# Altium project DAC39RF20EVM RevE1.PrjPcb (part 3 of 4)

## Sheet LMK LVL Shift and Mux.SchDoc: <Update Title in Parameters>
size 431 x 279 mm; Date: Not shown in title block; ApprovedBy: Not shown in title block; CheckedBy: Not shown in title block; Author: Not shown in title block; CompanyName: Not shown in title block; Engineer: Not shown in title block; Organization: Not shown in title block; Address1: Not shown in title block; Address2: Not shown in title block; Address3: Not shown in title block; Address4: Not shown in title block; DocumentNumber: 1; Revision: Use project parameter SCH_Rev; SheetNumber: 12; SheetTotal: 21; PageSetup: Record=PageOptions¦CenterHorizontal=True¦CenterVertical=True¦PrintScale=1.00¦XCorrection=1.00¦YCorrection=1.00¦PrintKind=0¦BorderSize=5000000¦LeftOffset=0¦BottomOffset=0¦Orientation=2¦PaperLength=1000¦PaperWidth=1000¦Scale=100¦PaperSource=15¦PrintQuality=600¦MediaType=1¦DitherType=10¦PaperKind=Letter¦PrintScaleMode=1
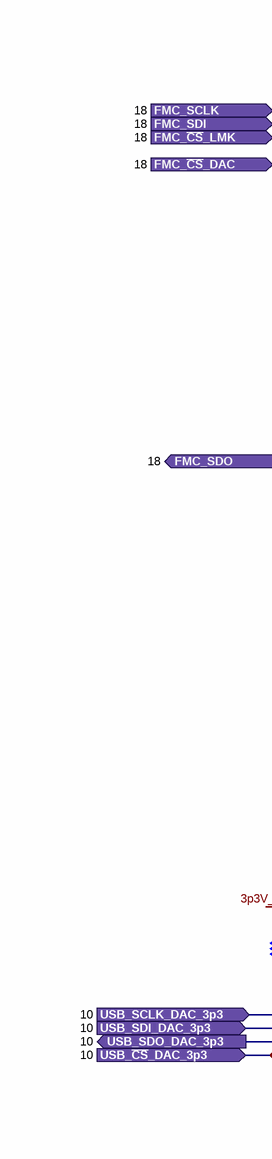
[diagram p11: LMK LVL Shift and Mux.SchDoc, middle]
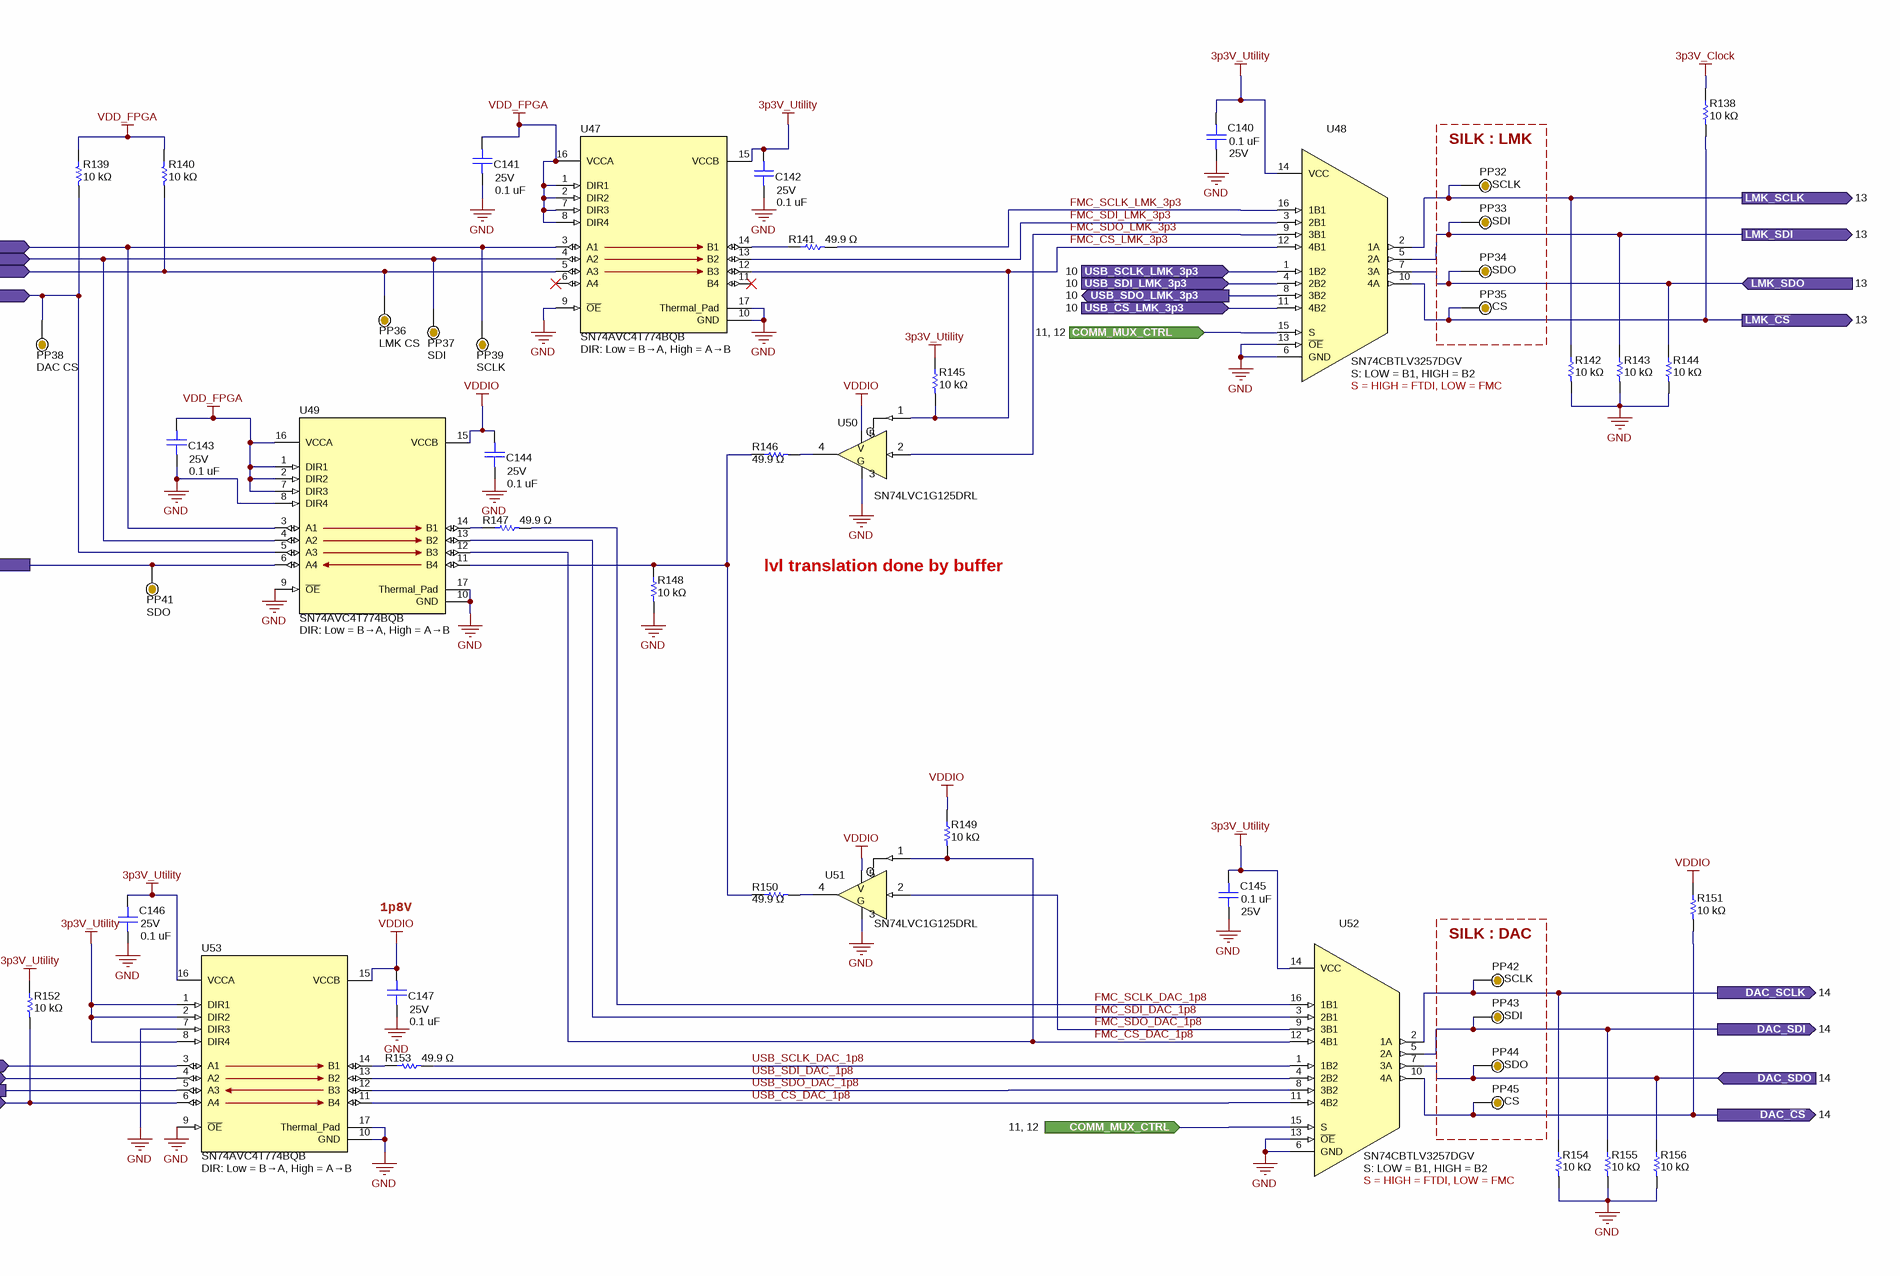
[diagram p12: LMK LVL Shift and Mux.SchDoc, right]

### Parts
C140  value 0.1 uF  Voltage - Rated: 25V  [0402L_cap]  (hidden comment: GRT155R71E104KE01J)
C141  value 0.1 uF  Voltage - Rated: 25V  [0402L_cap]  (hidden comment: GRT155R71E104KE01J)
C142  value 0.1 uF  Voltage - Rated: 25V  [0402L_cap]  (hidden comment: GRT155R71E104KE01J)
C143  value 0.1 uF  Voltage - Rated: 25V  [0402L_cap]  (hidden comment: GRT155R71E104KE01J)
C144  value 0.1 uF  Voltage - Rated: 25V  [0402L_cap]  (hidden comment: GRT155R71E104KE01J)
C145  value 0.1 uF  Voltage - Rated: 25V  [0402L_cap]  (hidden comment: GRT155R71E104KE01J)
C146  value 0.1 uF  Voltage - Rated: 25V  [0402L_cap]  (hidden comment: GRT155R71E104KE01J)
C147  value 0.1 uF  Voltage - Rated: 25V  [0402L_cap]  (hidden comment: GRT155R71E104KE01J)
PP32  Text1: SCLK  [ProbePoint_TH_40mil]  (hidden comment: Probe Point)  (no BOM)
PP33  Text1: SDI  [ProbePoint_TH_40mil]  (hidden comment: Probe Point)  (no BOM)
PP34  Text1: SDO  [ProbePoint_TH_40mil]  (hidden comment: Probe Point)  (no BOM)
PP35  Text1: CS  [ProbePoint_TH_40mil]  (hidden comment: Probe Point)  (no BOM)
PP36  Text1: LMK CS  [ProbePoint_TH_40mil]  (hidden comment: Probe Point)  (no BOM)
PP37  Text1: SDI  [ProbePoint_TH_40mil]  (hidden comment: Probe Point)  (no BOM)
PP38  Text1: DAC CS  [ProbePoint_TH_40mil]  (hidden comment: Probe Point)  (no BOM)
PP39  Text1: SCLK  [ProbePoint_TH_40mil]  (hidden comment: Probe Point)  (no BOM)
PP41  Text1: SDO  [ProbePoint_TH_40mil]  (hidden comment: Probe Point)  (no BOM)
PP42  Text1: SCLK  [ProbePoint_TH_40mil]  (hidden comment: Probe Point)  (no BOM)
PP43  Text1: SDI  [ProbePoint_TH_40mil]  (hidden comment: Probe Point)  (no BOM)
PP44  Text1: SDO  [ProbePoint_TH_40mil]  (hidden comment: Probe Point)  (no BOM)
PP45  Text1: CS  [ProbePoint_TH_40mil]  (hidden comment: Probe Point)  (no BOM)
R138  value 10 kΩ  [0201]  (hidden comment: ERJ-1GNF1002C)
R139  value 10 kΩ  [0201]  (hidden comment: ERJ-1GNF1002C)
R140  value 10 kΩ  [0201]  (hidden comment: ERJ-1GNF1002C)
R141  value 49.9 Ω  [0201]  (hidden comment: ERJ-1GNF49R9C)
R142  value 10 kΩ  [0201]  (hidden comment: ERJ-1GNF1002C)
R143  value 10 kΩ  [0201]  (hidden comment: ERJ-1GNF1002C)
R144  value 10 kΩ  [0201]  (hidden comment: ERJ-1GNF1002C)
R145  value 10 kΩ  [0201]  (hidden comment: ERJ-1GNF1002C)
R146  value 49.9 Ω  [0201]  (hidden comment: ERJ-1GNF49R9C)
R147  value 49.9 Ω  [0201]  (hidden comment: ERJ-1GNF49R9C)
R148  value 10 kΩ  [0201]  (hidden comment: ERJ-1GNF1002C)
R149  value 10 kΩ  [0201]  (hidden comment: ERJ-1GNF1002C)
R150  value 49.9 Ω  [0201]  (hidden comment: ERJ-1GNF49R9C)
R151  value 10 kΩ  [0201]  (hidden comment: ERJ-1GNF1002C)
R152  value 10 kΩ  [0201]  (hidden comment: ERJ-1GNF1002C)
R153  value 49.9 Ω  [0201]  (hidden comment: ERJ-1GNF49R9C)
R154  value 10 kΩ  [0201]  (hidden comment: ERJ-1GNF1002C)
R155  value 10 kΩ  [0201]  (hidden comment: ERJ-1GNF1002C)
R156  value 10 kΩ  [0201]  (hidden comment: ERJ-1GNF1002C)
U47  SN74AVC4T774BQB  Text1: DIR: Low = B→A, High = A→B  [BQB0016A-MFG]
U48  SN74CBTLV3257DGV  Text1: S: LOW = B1, HIGH = B2  [RSV0016A]
U49  SN74AVC4T774BQB  Text1: DIR: Low = B→A, High = A→B  [BQB0016A-MFG]
U50  SN74LVC1G125DRL  [DRL0005A]
U51  SN74LVC1G125DRL  [DRL0005A]
U52  SN74CBTLV3257DGV  Text1: S: LOW = B1, HIGH = B2  [RSV0016A]
U53  SN74AVC4T774BQB  Text1: DIR: Low = B→A, High = A→B  [BQB0016A-MFG]

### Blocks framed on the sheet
SILK : LMK: PP32-PP35
SILK : DAC: PP42-PP45

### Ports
COMM_MUX_CTRL (in, see 11, 12), DAC_SCLK (out, see 14), DAC_SDI (out, see 14), DAC_SDO (in, see 14), DAC_~{CS} (out, see 14), FMC_SCLK (in, see 18), FMC_SDI (in, see 18), FMC_SDO (out, see 18), FMC_~{CS}_DAC (in, see 18), FMC_~{CS}_LMK (in, see 18), LMK_SCLK (out, see 13), LMK_SDI (out, see 13), LMK_SDO (in, see 13), LMK_~{CS} (out, see 13), USB_SCLK_DAC_3p3 (in, see 10), USB_SCLK_LMK_3p3 (in, see 10), USB_SDI_DAC_3p3 (in, see 10), USB_SDI_LMK_3p3 (in, see 10), USB_SDO_DAC_3p3 (out, see 10), USB_SDO_LMK_3p3 (out, see 10), USB_~{CS}_DAC_3p3 (in, see 10), USB_~{CS}_LMK_3p3 (in, see 10)

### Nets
3p3V_Clock: R138.1
3p3V_Utility: C140.2 C142.1 C145.2 C146.2 R145.1 R152.1 U47.15(VCCB) U48.14(VCC) U52.14(VCC) U53.1(DIR1) U53.2(DIR2) U53.8(DIR4) U53.16(VCCA)
GND: C140.1 C141.2 C142.2 C143.2 C144.2 C145.1 C146.1 C147.2 R142.2 R143.2 R144.2 R148.2 R154.2 R155.2 R156.2 U47.9(~{OE}) U47.10(GND) U47.17(Thermal_Pad) U48.6(GND) U48.13(~{OE}) U49.8(DIR4) U49.9(~{OE}) U49.10(GND) U49.17(Thermal_Pad) U50.3(GND) U51.3(GND) U52.6(GND) U52.13(~{OE}) U53.7(DIR3) U53.9(~{OE}) U53.10(GND) U53.17(Thermal_Pad)
VDD_FPGA: C141.1 C143.1 R139.1 R140.1 U47.1(DIR1) U47.2(DIR2) U47.7(DIR3) U47.8(DIR4) U47.16(VCCA) U49.1(DIR1) U49.2(DIR2) U49.7(DIR3) U49.16(VCCA)
VDDIO: C144.1 C147.1 R149.1 R151.1 U49.15(VCCB) U50.5(VCC) U51.5(VCC) U53.15(VCCB)
COMM_MUX_CTRL: U48.15(S) U52.15(S) ; port COMM_MUX_CTRL
DAC_~{CS}: PP45.1 R151.2 U52.10(4A) ; port DAC_~{CS}
DAC_SCLK: PP42.1 R154.1 U52.2(1A) ; port DAC_SCLK
DAC_SDI: PP43.1 R155.1 U52.5(2A) ; port DAC_SDI
DAC_SDO: PP44.1 R156.1 U52.7(3A) ; port DAC_SDO
FMC_~{CS}_DAC: PP38.1 R139.2 U49.5(A3) ; port FMC_~{CS}_DAC
FMC_~{CS}_LMK: PP36.1 R140.2 U47.5(A3) ; port FMC_~{CS}_LMK
FMC_~{CS}_LMK_3p3: R145.2 U47.12(B3) U48.12(4B1) U50.1(~{OE})
FMC_CS_DAC_1p8: R149.2 U49.12(B3) U51.1(~{OE}) U52.12(4B1)
FMC_SCLK: PP39.1 U47.3(A1) U49.3(A1) ; port FMC_SCLK
FMC_SCLK_DAC_1p8: R147.2 U52.16(1B1)
FMC_SCLK_LMK_3p3: R141.2 U48.16(1B1)
FMC_SDI: PP37.1 U47.4(A2) U49.4(A2) ; port FMC_SDI
FMC_SDI_DAC_1p8: U49.13(B2) U52.3(2B1)
FMC_SDI_LMK_3p3: U47.13(B2) U48.3(2B1)
FMC_SDO: PP41.1 U49.6(A4) ; port FMC_SDO
FMC_SDO_DAC_1p8: U51.2(A) U52.9(3B1)
FMC_SDO_LMK_3p3: U48.9(3B1) U50.2(A)
LMK_~{CS}: PP35.1 R138.2 U48.10(4A) ; port LMK_~{CS}
LMK_SCLK: PP32.1 R142.1 U48.2(1A) ; port LMK_SCLK
LMK_SDI: PP33.1 R143.1 U48.5(2A) ; port LMK_SDI
LMK_SDO: PP34.1 R144.1 U48.7(3A) ; port LMK_SDO
USB_~{CS}_DAC_3p3: R152.2 U53.6(A4) ; port USB_~{CS}_DAC_3p3
USB_~{CS}_LMK_3p3: U48.11(4B2) ; port USB_~{CS}_LMK_3p3
USB_CS_DAC_1p8: U52.11(4B2) U53.11(B4)
USB_SCLK_DAC_1p8: R153.2 U52.1(1B2)
USB_SCLK_DAC_3p3: U53.3(A1) ; port USB_SCLK_DAC_3p3
USB_SCLK_LMK_3p3: U48.1(1B2) ; port USB_SCLK_LMK_3p3
USB_SDI_DAC_1p8: U52.4(2B2) U53.13(B2)
USB_SDI_DAC_3p3: U53.4(A2) ; port USB_SDI_DAC_3p3
USB_SDI_LMK_3p3: U48.4(2B2) ; port USB_SDI_LMK_3p3
USB_SDO_DAC_1p8: U52.8(3B2) U53.12(B3)
USB_SDO_DAC_3p3: U53.5(A3) ; port USB_SDO_DAC_3p3
USB_SDO_LMK_3p3: U48.8(3B2) ; port USB_SDO_LMK_3p3
NetR141_1: R141.1 U47.14(B1)
NetR146_1: R146.1 R148.1 R150.1 U49.11(B4)
NetR146_2: R146.2 U50.4(Y)
NetR147_1: R147.1 U49.14(B1)
NetR150_2: R150.2 U51.4(Y)
NetR153_1: R153.1 U53.14(B1)

Not connected (* = marked no-connect by the designer): U47 6(A4)* 11(B4)*

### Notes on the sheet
- (near U48) S = HIGH = FTDI, LOW = FMC
- lvl translation done by buffer
- 1p8V
- (near U52) S = HIGH = FTDI, LOW = FMC

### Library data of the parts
C140-C147 = capcc09401: CAP CER 0.1UF 25V X7R 0402; Manufacturer: Murata; SizeZ_mm: 0.7; SizeX_mm: 1; SizeY_mm: 0.5; CompType: Capacitor Ceramic; Tolerance: ±10%
PP32-PP39 PP41-PP45 = Probe Point: Probe Point that can be used in lue of a test point; UniqueID: cmp00025
R138-R140 R142-R145 R148 R149 R151 R152 R154-R156 = RSMD020100762: RES SMD 10K OHM 1% 1/20W 0201; Manufacturer: Panasonic Electronic Components; CompType: Resistor SMD; Power (Watts): 0.05W, 1/20W; Temperature Coefficient: ±200ppm/°C
R141 R146 R147 R150 R153 = RSMD020100177: RES SMD 49.9 OHM 1% 1/20W 0201; Manufacturer: Panasonic Electronic Components; CompType: Resistor SMD; Power (Watts): 0.05W, 1/20W; Temperature Coefficient: ±200ppm/°C
U47 U49 U53 = cmp00170: Translation - Voltage Levels 4-bit dual-supply bus transceiver with 3-state outputs and independent direction control inputs; Manufacturer: Texas Instruments; Alt PartNumber: SN74AXC4T774BQB; CompType: Level Shifter
U48 U52 = SN74CBTLV3257RSV: Low-Voltage 4-Bit 1-of-2 FET Multiplexer/Demultiplexe; PartNumber: SN74CBTLV3257RSVR; Manufacturer: Texas Instruments; UniqueID: cmp00269; CompType: MUX
U50 U51 = SN74LVC1G125DRL: Single Bus Buffer Gate With 3-State Outputs; Manufacturer: Texas Instruments; UniqueID: cmp00472

## Sheet Clocking LMK04828.SchDoc: LMK Clocking Fanout
size 431 x 279 mm; Date: Not shown in title block; ApprovedBy: Not shown in title block; CheckedBy: Not shown in title block; Author: Not shown in title block; CompanyName: Not shown in title block; Engineer: Not shown in title block; Organization: Not shown in title block; Address1: Not shown in title block; Address2: Not shown in title block; Address3: Not shown in title block; Address4: Not shown in title block; DocumentNumber: 1; Revision: Use project parameter SCH_Rev; SheetNumber: 13; SheetTotal: 21; PageSetup: Record=PageOptions¦CenterHorizontal=True¦CenterVertical=True¦PrintScale=1.00¦XCorrection=1.00¦YCorrection=1.00¦PrintKind=0¦BorderSize=5000000¦LeftOffset=0¦BottomOffset=0¦Orientation=2¦PaperLength=1000¦PaperWidth=1000¦Scale=100¦PaperSource=15¦PrintQuality=600¦MediaType=1¦DitherType=10¦PaperKind=Letter¦PrintScaleMode=1
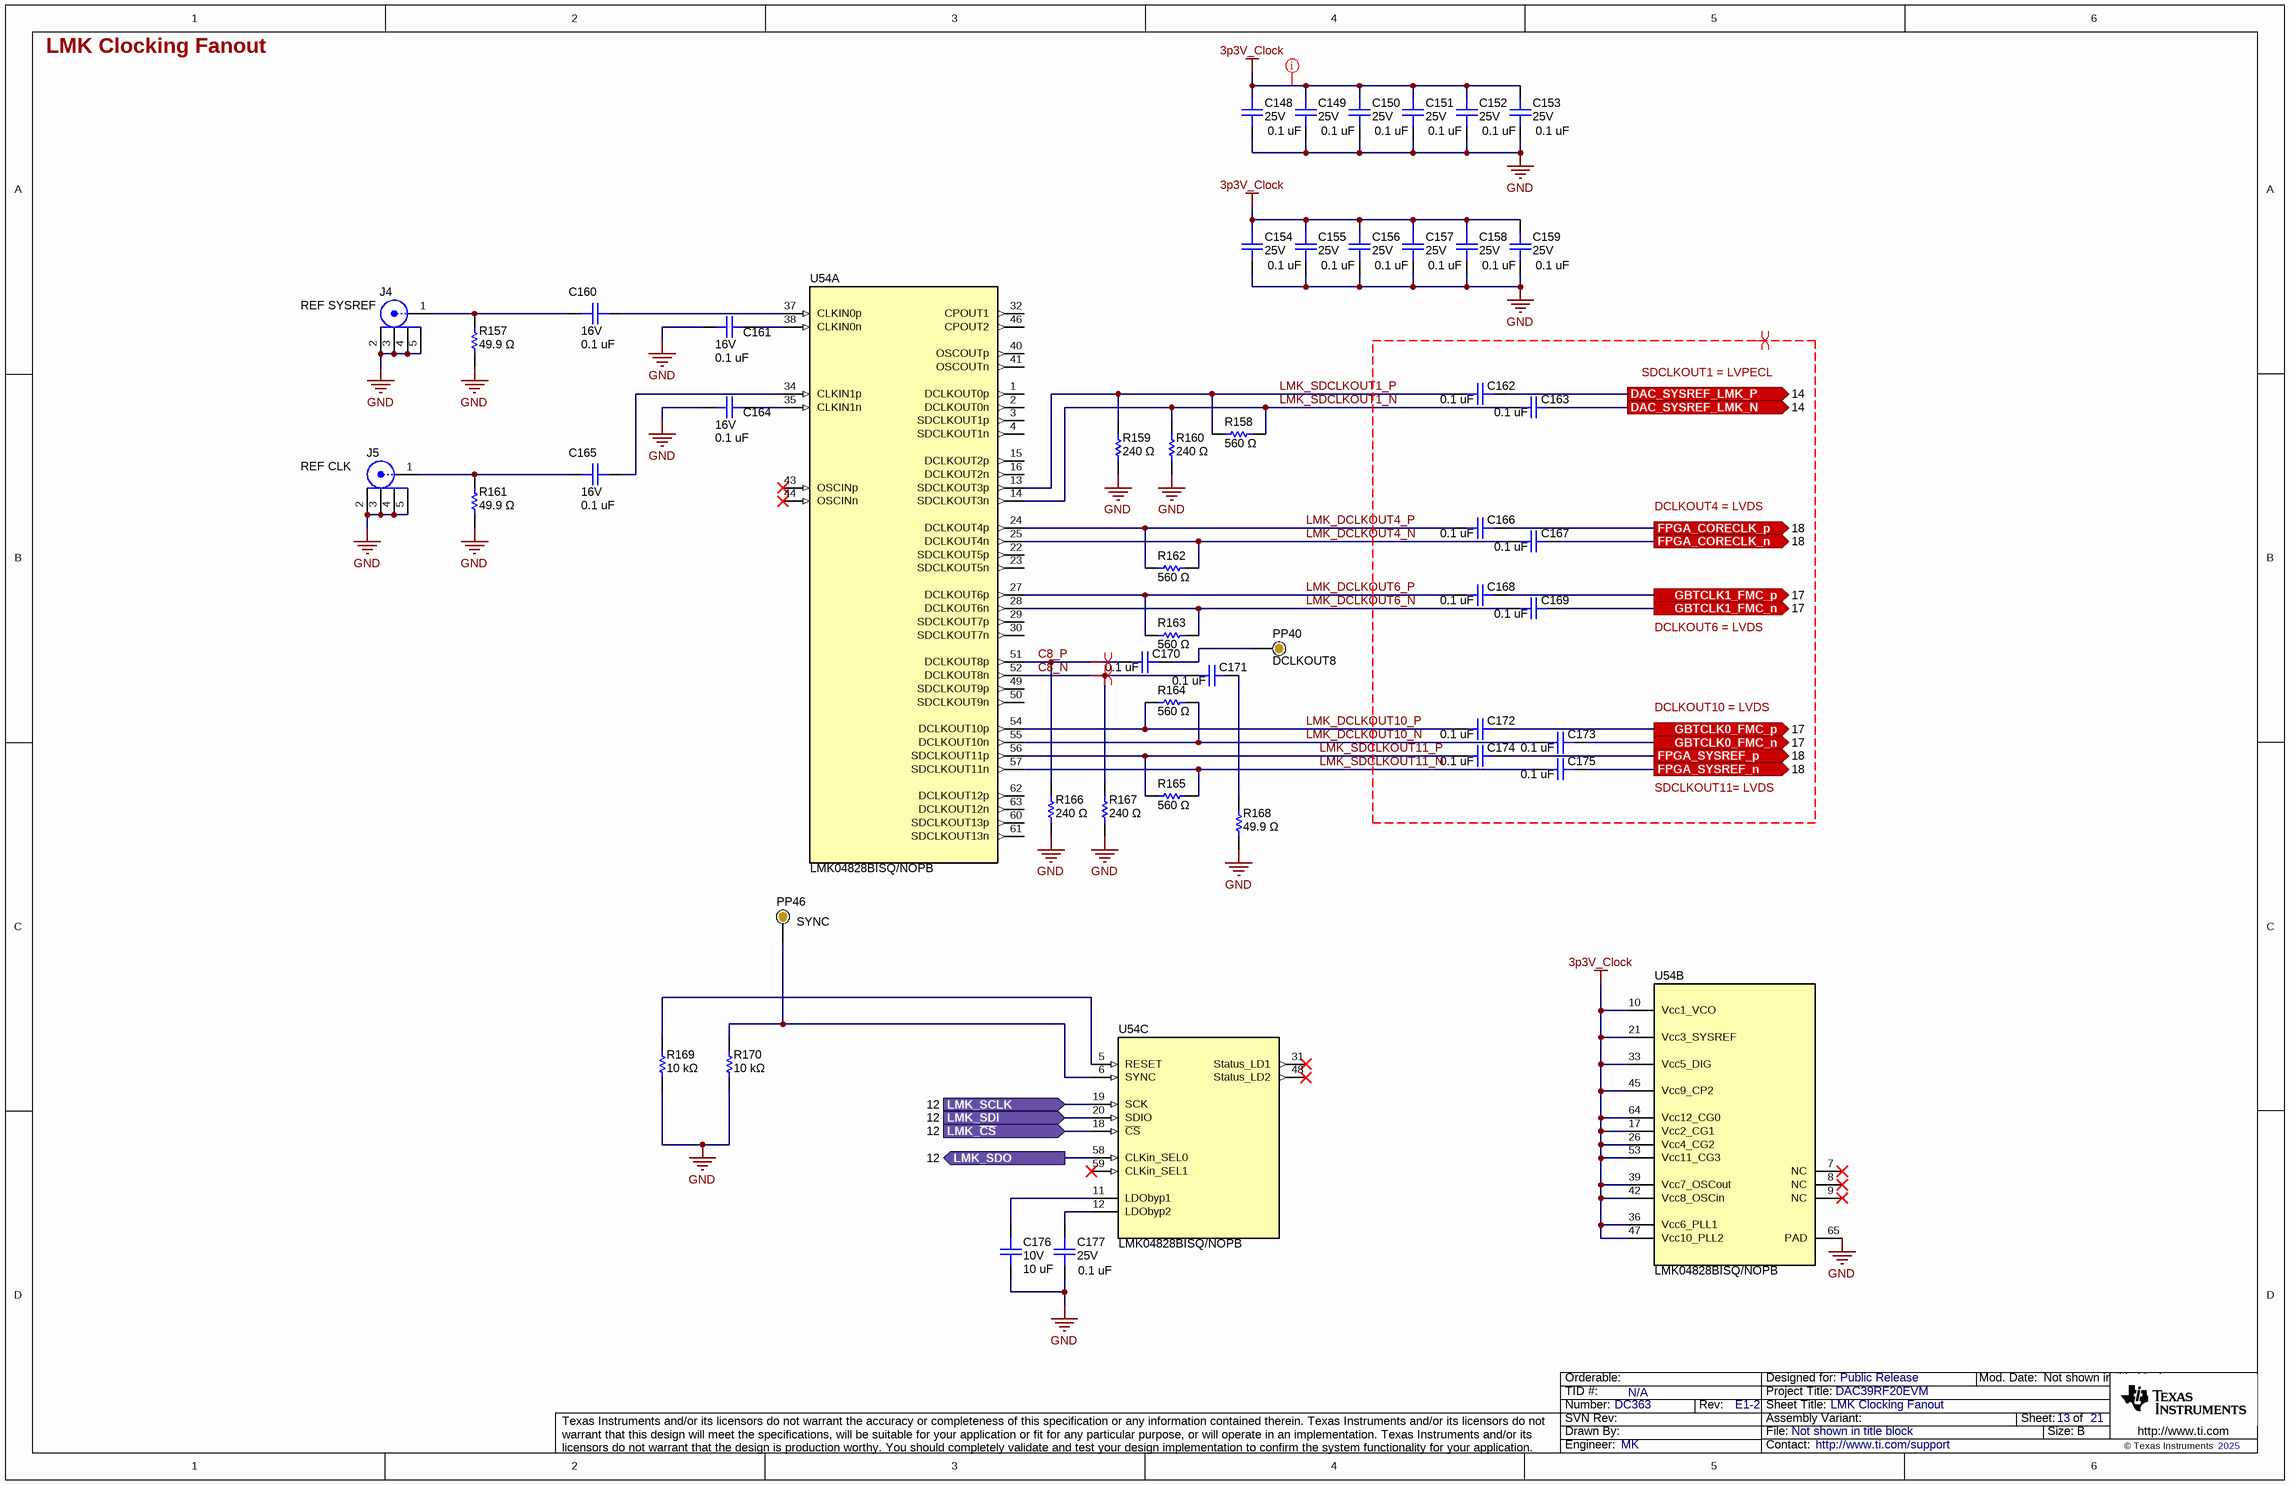
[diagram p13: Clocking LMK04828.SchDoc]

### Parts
C148  value 0.1 uF  Voltage - Rated: 25V  [0402L_cap]  (hidden comment: GRT155R71E104KE01J)
C149  value 0.1 uF  Voltage - Rated: 25V  [0402L_cap]  (hidden comment: GRT155R71E104KE01J)
C150  value 0.1 uF  Voltage - Rated: 25V  [0402L_cap]  (hidden comment: GRT155R71E104KE01J)
C151  value 0.1 uF  Voltage - Rated: 25V  [0402L_cap]  (hidden comment: GRT155R71E104KE01J)
C152  value 0.1 uF  Voltage - Rated: 25V  [0402L_cap]  (hidden comment: GRT155R71E104KE01J)
C153  value 0.1 uF  Voltage - Rated: 25V  [0402L_cap]  (hidden comment: GRT155R71E104KE01J)
C154  value 0.1 uF  Voltage - Rated: 25V  [0402L_cap]  (hidden comment: GRT155R71E104KE01J)
C155  value 0.1 uF  Voltage - Rated: 25V  [0402L_cap]  (hidden comment: GRT155R71E104KE01J)
C156  value 0.1 uF  Voltage - Rated: 25V  [0402L_cap]  (hidden comment: GRT155R71E104KE01J)
C157  value 0.1 uF  Voltage - Rated: 25V  [0402L_cap]  (hidden comment: GRT155R71E104KE01J)
C158  value 0.1 uF  Voltage - Rated: 25V  [0402L_cap]  (hidden comment: GRT155R71E104KE01J)
C159  value 0.1 uF  Voltage - Rated: 25V  [0402L_cap]  (hidden comment: GRT155R71E104KE01J)
C160  value 0.1 uF  Voltage - Rated: 16V  [0201_cap]  (hidden comment: GRM033Z71C104KE14D)
C161  value 0.1 uF  Voltage - Rated: 16V  [0201_cap]  (hidden comment: GRM033Z71C104KE14D)
C162  value 0.1 uF  [0201_cap]  (hidden comment: GRM033Z71C104KE14D)
C163  value 0.1 uF  [0201_cap]  (hidden comment: GRM033Z71C104KE14D)
C164  value 0.1 uF  Voltage - Rated: 16V  [0201_cap]  (hidden comment: GRM033Z71C104KE14D)
C165  value 0.1 uF  Voltage - Rated: 16V  [0201_cap]  (hidden comment: GRM033Z71C104KE14D)
C166  value 0.1 uF  [0201_cap]  (hidden comment: GRM033Z71C104KE14D)
C167  value 0.1 uF  [0201_cap]  (hidden comment: GRM033Z71C104KE14D)
C168  value 0.1 uF  [0201_cap]  (hidden comment: GRM033Z71C104KE14D)
C169  value 0.1 uF  [0201_cap]  (hidden comment: GRM033Z71C104KE14D)
C170  value 0.1 uF  [0201_cap]  (hidden comment: GRM033Z71C104KE14D)
C171  value 0.1 uF  [0201_cap]  (hidden comment: GRM033Z71C104KE14D)
C172  value 0.1 uF  [0201_cap]  (hidden comment: GRM033Z71C104KE14D)
C173  value 0.1 uF  [0201_cap]  (hidden comment: GRM033Z71C104KE14D)
C174  value 0.1 uF  [0201_cap]  (hidden comment: GRM033Z71C104KE14D)
C175  value 0.1 uF  [0201_cap]  (hidden comment: GRM033Z71C104KE14D)
C176  value 10 uF  Voltage - Rated: 10V  [0603L_cap]  (hidden comment: C1608X5R1A106K080AC)
C177  value 0.1 uF  Voltage - Rated: 25V  [0402L_cap]  (hidden comment: GRT155R71E104KE01J)
J4  Text1: REF SYSREF  [FP-132134-15_CONN_SMA_JACK-MFG]  (hidden comment: 132134-15)
J5  Text1: REF CLK  [FP-132134-15_CONN_SMA_JACK-MFG]  (hidden comment: 132134-15)
PP40  Text1: DCLKOUT8  [ProbePoint_TH_40mil]  (hidden comment: Probe Point)  (no BOM)
PP46  Text1: SYNC  [ProbePoint_TH_40mil]  (hidden comment: Probe Point)  (no BOM)
R157  value 49.9 Ω  [0201]  (hidden comment: ERJ-1GNF49R9C)
R158  value 560 Ω  [0201]  (hidden comment: ERJ-U01J561C)
R159  value 240 Ω  [0201]  (hidden comment: ERJ-1GNF2400C)
R160  value 240 Ω  [0201]  (hidden comment: ERJ-1GNF2400C)
R161  value 49.9 Ω  [0201]  (hidden comment: ERJ-1GNF49R9C)
R162  value 560 Ω  [0201]  (hidden comment: ERJ-U01J561C)
R163  value 560 Ω  [0201]  (hidden comment: ERJ-U01J561C)
R164  value 560 Ω  [0201]  (hidden comment: ERJ-U01J561C)
R165  value 560 Ω  [0201]  (hidden comment: ERJ-U01J561C)
R166  value 240 Ω  [0201]  (hidden comment: ERJ-1GNF2400C)
R167  value 240 Ω  [0201]  (hidden comment: ERJ-1GNF2400C)
R168  value 49.9 Ω  [0201]  (hidden comment: ERJ-1GNF49R9C)
R169  value 10 kΩ  [0402L]  (hidden comment: ERJ-H2RF1002X)
R170  value 10 kΩ  [0402L]  (hidden comment: ERJ-H2RF1002X)
U54  LMK04828BISQ/NOPB  [NKD0064A]  (parts A,B,C of 3)

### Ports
DAC_SYSREF_LMK_N (out, see 14), DAC_SYSREF_LMK_P (out, see 14), FPGA_CORECLK_n (out, see 18), FPGA_CORECLK_p (out, see 18), FPGA_SYSREF_n (out, see 18), FPGA_SYSREF_p (out, see 18), GBTCLK0_FMC_n (out, see 17), GBTCLK0_FMC_p (out, see 17), GBTCLK1_FMC_n (out, see 17), GBTCLK1_FMC_p (out, see 17), LMK_SCLK (in, see 12), LMK_SDI (in, see 12), LMK_SDO (out, see 12), LMK_~{CS} (in, see 12)

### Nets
3p3V_Clock: C148.1 C149.1 C150.1 C151.1 C152.1 C153.1 C154.1 C155.1 C156.1 C157.1 C158.1 C159.1 U54.10(Vcc1_VCO) U54.17(Vcc2_CG1) U54.21(Vcc3_SYSREF) U54.26(Vcc4_CG2) U54.33(Vcc5_DIG) U54.36(Vcc6_PLL1) U54.39(Vcc7_OSCout) U54.42(Vcc8_OSCin) U54.45(Vcc9_CP2) U54.47(Vcc10_PLL2) U54.53(Vcc11_CG3) U54.64(Vcc12_CG0)
GND: C148.2 C149.2 C150.2 C151.2 C152.2 C153.2 C154.2 C155.2 C156.2 C157.2 C158.2 C159.2 C161.1 C164.1 C176.1 C177.2 J4.2 J4.3 J4.4 J4.5 J5.2 J5.3 J5.4 J5.5 R157.1 R159.1 R160.1 R161.1 R166.1 R167.1 R168.1 R169.1 R170.1 U54.65(PAD)
C8_N: C171.2 R167.2 U54.52(DCLKOUT8n)
C8_P: C170.2 R166.2 U54.51(DCLKOUT8p)
DAC_SYSREF_LMK_N: C163.1 ; port DAC_SYSREF_LMK_N
DAC_SYSREF_LMK_P: C162.1 ; port DAC_SYSREF_LMK_P
FPGA_CORECLK_n: C167.1 ; port FPGA_CORECLK_n
FPGA_CORECLK_p: C166.1 ; port FPGA_CORECLK_p
FPGA_SYSREF_n: C175.1 ; port FPGA_SYSREF_n
FPGA_SYSREF_p: C174.1 ; port FPGA_SYSREF_p
GBTCLK0_FMC_n: C173.1 ; port GBTCLK0_FMC_n
GBTCLK0_FMC_p: C172.1 ; port GBTCLK0_FMC_p
GBTCLK1_FMC_n: C169.1 ; port GBTCLK1_FMC_n
GBTCLK1_FMC_p: C168.1 ; port GBTCLK1_FMC_p
LMK_~{CS}: U54.18(~{CS}) ; port LMK_~{CS}
LMK_DCLKOUT4_N: C167.2 R162.2 U54.25(DCLKOUT4n)
LMK_DCLKOUT4_P: C166.2 R162.1 U54.24(DCLKOUT4p)
LMK_DCLKOUT6_N: C169.2 R163.2 U54.28(DCLKOUT6n)
LMK_DCLKOUT6_P: C168.2 R163.1 U54.27(DCLKOUT6p)
LMK_DCLKOUT10_N: C173.2 R164.2 U54.55(DCLKOUT10n)
LMK_DCLKOUT10_P: C172.2 R164.1 U54.54(DCLKOUT10p)
LMK_SCLK: U54.19(SCK) ; port LMK_SCLK
LMK_SDCLKOUT1_N: C163.2 R158.2 R160.2 U54.14(SDCLKOUT3n)
LMK_SDCLKOUT1_P: C162.2 R158.1 R159.2 U54.13(SDCLKOUT3p)
LMK_SDCLKOUT11_N: C175.2 R165.1 U54.57(SDCLKOUT11n)
LMK_SDCLKOUT11_P: C174.2 R165.2 U54.56(SDCLKOUT11p)
LMK_SDI: U54.20(SDIO) ; port LMK_SDI
LMK_SDO: U54.58(CLKin_SEL0) ; port LMK_SDO
NetC160_1: C160.1 J4.1 R157.2
NetC160_2: C160.2 U54.37(CLKIN0p)
NetC161_2: C161.2 U54.38(CLKIN0n)
NetC164_2: C164.2 U54.35(CLKIN1n)
NetC165_1: C165.1 J5.1 R161.2
NetC165_2: C165.2 U54.34(CLKIN1p)
NetC170_1: C170.1 PP40.1
NetC171_1: C171.1 R168.2
NetC176_2: C176.2 U54.11(LDObyp1)
NetC177_1: C177.1 U54.12(LDObyp2)
NetPP46_1: PP46.1 R170.2 U54.6(SYNC)
NetR169_2: R169.2 U54.5(RESET)

Not connected (* = marked no-connect by the designer): U54 1(DCLKOUT0p) 2(DCLKOUT0n) 3(SDCLKOUT1p) 4(SDCLKOUT1n) 7(NC)* 8(NC)* 9(NC)* 15(DCLKOUT2p) 16(DCLKOUT2n) 22(SDCLKOUT5p) 23(SDCLKOUT5n) 29(SDCLKOUT7p) 30(SDCLKOUT7n) 31(Status_LD1)* 32(CPOUT1) 40(OSCOUTp) 41(OSCOUTn) 43(OSCINp)* 44(OSCINn)* 46(CPOUT2) 48(Status_LD2)* 49(SDCLKOUT9p) 50(SDCLKOUT9n) 59(CLKin_SEL1)* 60(SDCLKOUT13p) 61(SDCLKOUT13n) 62(DCLKOUT12p) 63(DCLKOUT12n)

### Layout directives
net class Power; net class LMXK: 3p3V_Clock
differential pair; net class LMK_Clocks: (no net found under the mark), C8_N, C8_P

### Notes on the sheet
- SDCLKOUT1 = LVPECL
- DCLKOUT4 = LVDS
- DCLKOUT6 = LVDS
- DCLKOUT10 = LVDS
- SDCLKOUT11= LVDS

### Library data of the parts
C148-C159 C177 = capcc09401: as C140-C147 on sheet LMK LVL Shift and Mux
C160-C175 = capcc09263: CAP CER 0.1UF 16V X7R 0201; Manufacturer: Murata Electronics; CompType: Capacitor Ceramic; Tolerance: ±10%; SizeX_mm: 0.6; SizeY_mm: 0.3; SizeZ_mm: 0.33
C176 = capcc03566: CAP CER 10UF 10V X5R 0603; Manufacturer: TDK Corporation; CompType: Capacitor Ceramic; Tolerance: ±10%; SizeX_mm: 1.6; SizeY_mm: 0.8; SizeZ_mm: 0.9
J4 J5 = 132134-15: SMA Connector Jack, Female Socket 50Ohm Surface Mount, Through Hole Solder; Manufacturer: Amphenol RF; UniqueID: cmp00028; CompType: RF Connector
PP40 PP46 = Probe Point: as PP32-PP39 on sheet LMK LVL Shift and Mux
R157 R161 R168 = RSMD020100177: as R141 on sheet LMK LVL Shift and Mux
R158 R162-R165 = RSMD020101357: RES 560 OHM 5% 1/20W 0201 SMD; Manufacturer: Panasonic Electronic Components; CompType: Resistor SMD; Power (Watts): 0.05W, 1/20W; Temperature Coefficient: ±200ppm/°C
R159 R160 R166 R167 = RSMD020100105: RES SMD 240 OHM 1% 1/20W 0201; Manufacturer: Panasonic Electronic Components; CompType: Resistor SMD; Power (Watts): 0.05W, 1/20W; Temperature Coefficient: ±200ppm/°C
R169 R170 = RSMD040200316: RES 10K OHM 1% 1/10W 0402; Manufacturer: Panasonic Electronic Components; CompType: Resistor SMD; Power (Watts): 0.1W, 1/10W; Temperature Coefficient: ±100ppm/°C; SizeX_mm: 1; SizeY_mm: 0.5; SizeZ_mm: 0.4
U54 = LMK04828BISQ/NOPB: Ultra low-noise JESD204B compliant clock jitter cleaner with integrated 2370 to 2630-MHz VCO0; Manufacturer: Texas Instruments; Alt PartNumber: LMK04828BISQE/NOPB; CompType: Clocking; SizeX_mm: 9; SizeZ_mm: 0.8

## Sheet DUT IO.SchDoc: DAC I/O
size 431 x 279 mm; Date: Not shown in title block; ApprovedBy: Not shown in title block; CheckedBy: Not shown in title block; Author: Not shown in title block; CompanyName: Not shown in title block; Engineer: Not shown in title block; Organization: Not shown in title block; Address1: Not shown in title block; Address2: Not shown in title block; Address3: Not shown in title block; Address4: Not shown in title block; DocumentNumber: 1; Revision: Use project parameter SCH_Rev; SheetNumber: 14; SheetTotal: 21; PageSetup: Record=PageOptions¦CenterHorizontal=True¦CenterVertical=True¦PrintScale=1.00¦XCorrection=1.00¦YCorrection=1.00¦PrintKind=0¦BorderSize=5000000¦LeftOffset=0¦BottomOffset=0¦Orientation=2¦PaperLength=1000¦PaperWidth=1000¦Scale=100¦PaperSource=15¦PrintQuality=600¦MediaType=1¦DitherType=10¦PaperKind=Letter¦PrintScaleMode=1
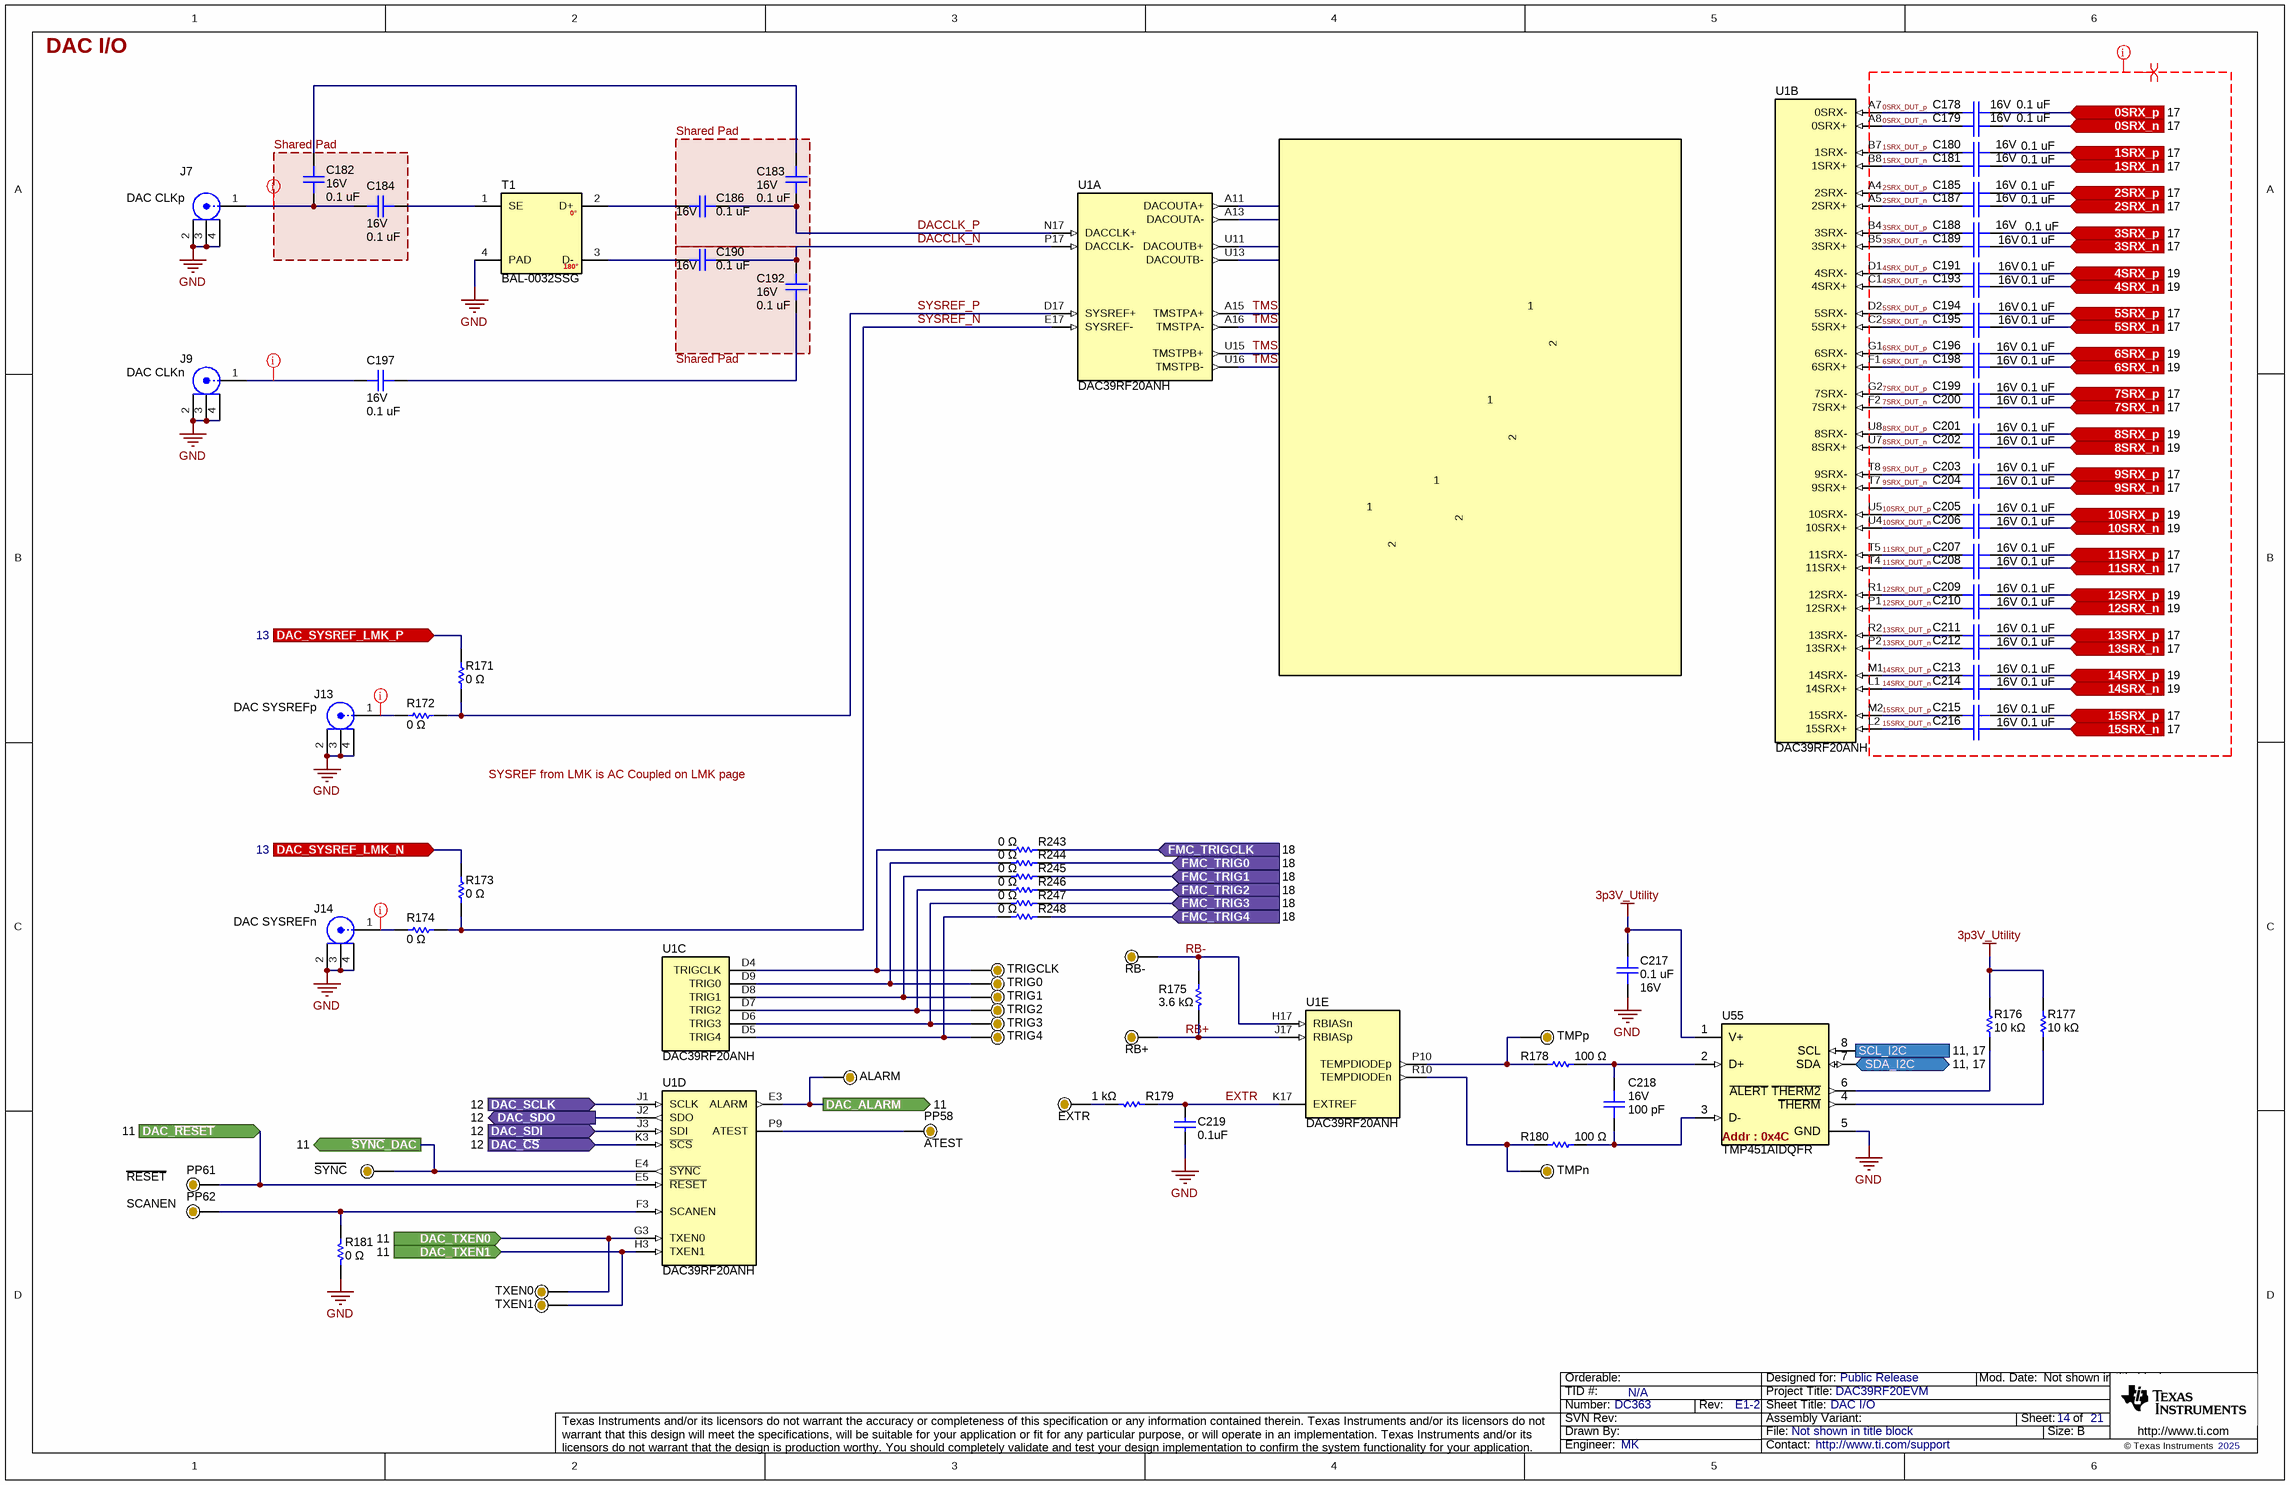
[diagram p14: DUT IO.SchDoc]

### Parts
(Parts that share a designator on the sheet are numbered #1, #2 ... from top to bottom, then left to right.)
?#1  Shared Pad  (graphical)
?#2  Shared Pad  (graphical)
?#3  Shared Pad  (graphical)
C178  value 0.1 uF  Voltage - Rated: 16V  [0201_cap]  (hidden comment: 0201BB104KW160)
C179  value 0.1 uF  Voltage - Rated: 16V  [0201_cap]  (hidden comment: 0201BB104KW160)
C180  value 0.1 uF  Voltage - Rated: 16V  [0201_cap]  (hidden comment: 0201BB104KW160)
C181  value 0.1 uF  Voltage - Rated: 16V  [0201_cap]  (hidden comment: 0201BB104KW160)
C182  value 0.1 uF  Voltage - Rated: 16V  [0201_cap]  (hidden comment: 0201BB104KW160)
C183  value 0.1 uF  Voltage - Rated: 16V  [0201_cap]  (hidden comment: 0201BB104KW160)
C184  value 0.1 uF  Voltage - Rated: 16V  [0201_cap]  (hidden comment: 0201BB104KW160)
C185  value 0.1 uF  Voltage - Rated: 16V  [0201_cap]  (hidden comment: 0201BB104KW160)
C186  value 0.1 uF  Voltage - Rated: 16V  [0201_cap]  (hidden comment: 0201BB104KW160)
C187  value 0.1 uF  Voltage - Rated: 16V  [0201_cap]  (hidden comment: 0201BB104KW160)
C188  value 0.1 uF  Voltage - Rated: 16V  [0201_cap]  (hidden comment: 0201BB104KW160)
C189  value 0.1 uF  Voltage - Rated: 16V  [0201_cap]  (hidden comment: 0201BB104KW160)
C190  value 0.1 uF  Voltage - Rated: 16V  [0201_cap]  (hidden comment: 0201BB104KW160)
C191  value 0.1 uF  Voltage - Rated: 16V  [0201_cap]  (hidden comment: 0201BB104KW160)
C192  value 0.1 uF  Voltage - Rated: 16V  [0201_cap]  (hidden comment: 0201BB104KW160)
C193  value 0.1 uF  Voltage - Rated: 16V  [0201_cap]  (hidden comment: 0201BB104KW160)
C194  value 0.1 uF  Voltage - Rated: 16V  [0201_cap]  (hidden comment: 0201BB104KW160)
C195  value 0.1 uF  Voltage - Rated: 16V  [0201_cap]  (hidden comment: 0201BB104KW160)
C196  value 0.1 uF  Voltage - Rated: 16V  [0201_cap]  (hidden comment: 0201BB104KW160)
C197  value 0.1 uF  Voltage - Rated: 16V  [0201_cap]  (hidden comment: 0201BB104KW160)
C198  value 0.1 uF  Voltage - Rated: 16V  [0201_cap]  (hidden comment: 0201BB104KW160)
C199  value 0.1 uF  Voltage - Rated: 16V  [0201_cap]  (hidden comment: 0201BB104KW160)
C200  value 0.1 uF  Voltage - Rated: 16V  [0201_cap]  (hidden comment: 0201BB104KW160)
C201  value 0.1 uF  Voltage - Rated: 16V  [0201_cap]  (hidden comment: 0201BB104KW160)
C202  value 0.1 uF  Voltage - Rated: 16V  [0201_cap]  (hidden comment: 0201BB104KW160)
C203  value 0.1 uF  Voltage - Rated: 16V  [0201_cap]  (hidden comment: 0201BB104KW160)
C204  value 0.1 uF  Voltage - Rated: 16V  [0201_cap]  (hidden comment: 0201BB104KW160)
C205  value 0.1 uF  Voltage - Rated: 16V  [0201_cap]  (hidden comment: 0201BB104KW160)
C206  value 0.1 uF  Voltage - Rated: 16V  [0201_cap]  (hidden comment: 0201BB104KW160)
C207  value 0.1 uF  Voltage - Rated: 16V  [0201_cap]  (hidden comment: 0201BB104KW160)
C208  value 0.1 uF  Voltage - Rated: 16V  [0201_cap]  (hidden comment: 0201BB104KW160)
C209  value 0.1 uF  Voltage - Rated: 16V  [0201_cap]  (hidden comment: 0201BB104KW160)
C210  value 0.1 uF  Voltage - Rated: 16V  [0201_cap]  (hidden comment: 0201BB104KW160)
C211  value 0.1 uF  Voltage - Rated: 16V  [0201_cap]  (hidden comment: 0201BB104KW160)
C212  value 0.1 uF  Voltage - Rated: 16V  [0201_cap]  (hidden comment: 0201BB104KW160)
C213  value 0.1 uF  Voltage - Rated: 16V  [0201_cap]  (hidden comment: 0201BB104KW160)
C214  value 0.1 uF  Voltage - Rated: 16V  [0201_cap]  (hidden comment: 0201BB104KW160)
C215  value 0.1 uF  Voltage - Rated: 16V  [0201_cap]  (hidden comment: 0201BB104KW160)
C216  value 0.1 uF  Voltage - Rated: 16V  [0201_cap]  (hidden comment: 0201BB104KW160)
C217  value 0.1 uF  Voltage - Rated: 16V  [0201_cap]  (hidden comment: GRM033Z71C104KE14D)
C218  value 100 pF  Voltage - Rated: 16V  [0201_cap]  (hidden comment: GRM033R71C101JA01D)
C219  ValueDisplayed: 0.1uF  [0201L]  (hidden comment: GRM033Z71C104KE14D)
J7  Text1: DAC CLKp  [HiRose-HK-LR-SR2-SWM1092-04A-MicroStirp-6mil-Female-Backdrill]  (hidden comment: HK-LR-SR2(11))
J8  Text1: TSTAp  [Molex_0853050232]  (hidden comment: 0853050232)
J9  Text1: DAC CLKn  [HiRose-HK-LR-SR2-SWM1092-04A-MicroStirp-6mil-Female-Backdrill]  (hidden comment: HK-LR-SR2(11))
J10  Text1: TSTAn  [Molex_0853050232]  (hidden comment: 0853050232)
J11  Text1: TSTBp  [Molex_0853050232]  (hidden comment: 0853050232)
J12  Text1: TSTBn  [Molex_0853050232]  (hidden comment: 0853050232)
J13  Text1: DAC SYSREFp  [HiRose-HK-LR-SR2-SWM1092-04A-MicroStirp-6mil-Female-Backdrill]  (hidden comment: HK-LR-SR2(11))
J14  Text1: DAC SYSREFn  [HiRose-HK-LR-SR2-SWM1092-04A-MicroStirp-6mil-Female-Backdrill]  (hidden comment: HK-LR-SR2(11))
PP47  Text1: RB-  [ProbePoint_TH_40mil]  (hidden comment: Probe Point)  (no BOM)
PP48  Text1: TRIGCLK  [ProbePoint_TH_40mil]  (hidden comment: Probe Point)  (no BOM)
PP49  Text1: TRIG0  [ProbePoint_TH_40mil]  (hidden comment: Probe Point)  (no BOM)
PP50  Text1: TRIG1  [ProbePoint_TH_40mil]  (hidden comment: Probe Point)  (no BOM)
PP51  Text1: TRIG2  [ProbePoint_TH_40mil]  (hidden comment: Probe Point)  (no BOM)
PP52  Text1: TRIG3  [ProbePoint_TH_40mil]  (hidden comment: Probe Point)  (no BOM)
PP53  Text1: TRIG4  [ProbePoint_TH_40mil]  (hidden comment: Probe Point)  (no BOM)
PP54  Text1: RB+  [ProbePoint_TH_40mil]  (hidden comment: Probe Point)  (no BOM)
PP55  Text1: TMPp  [ProbePoint_TH_40mil]  (hidden comment: Probe Point)  (no BOM)
PP56  Text1: ALARM  [ProbePoint_TH_40mil]  (hidden comment: Probe Point)  (no BOM)
PP57  Text1: EXTR  [ProbePoint_TH_40mil]  (hidden comment: Probe Point)  (no BOM)
PP58  Text1: ATEST  [ProbePoint_TH_40mil]  (hidden comment: Probe Point)  (no BOM)
PP59  Text1: SYNC  [ProbePoint_TH_40mil]  (hidden comment: Probe Point)  (no BOM)
PP60  Text1: TMPn  [ProbePoint_TH_40mil]  (hidden comment: Probe Point)  (no BOM)
PP61  Text1: RESET  [ProbePoint_TH_40mil]  (hidden comment: Probe Point)  (no BOM)
PP62  Text1: SCANEN  [ProbePoint_TH_40mil]  (hidden comment: Probe Point)  (no BOM)
PP63  Text1: TXEN0  [ProbePoint_TH_40mil]  (hidden comment: Probe Point)  (no BOM)
PP64  Text1: TXEN1  [ProbePoint_TH_40mil]  (hidden comment: Probe Point)  (no BOM)
R171  value 0 Ω  [0201]  (hidden comment: ERJ-1GN0R00C)
R172  value 0 Ω  [0201]  (hidden comment: ERJ-1GN0R00C)
R173  value 0 Ω  [0201]  (hidden comment: ERJ-1GN0R00C)
R174  value 0 Ω  [0201]  (hidden comment: ERJ-1GN0R00C)
R175  value 3.6 kΩ  [0201]  (hidden comment: ERJ-1GNF3601C)
R176  value 10 kΩ  [0201]  (hidden comment: ERJ-U01F1002C)
R177  value 10 kΩ  [0201]  (hidden comment: ERJ-U01F1002C)
R178  value 100 Ω  [0201L]  (hidden comment: ERJ-1GNF1000C)
R179  value 1 kΩ  [0201]  (hidden comment: ERJ-1GNF1001C)
R180  value 100 Ω  [0201L]  (hidden comment: ERJ-1GNF1000C)
R181  value 0 Ω  [0201]  (hidden comment: ERJ-1GN0R00C)
R243  value 0 Ω  [0201]  (hidden comment: ERJ-1GN0R00C)
R244  value 0 Ω  [0201]  (hidden comment: ERJ-1GN0R00C)
R245  value 0 Ω  [0201]  (hidden comment: ERJ-1GN0R00C)
R246  value 0 Ω  [0201]  (hidden comment: ERJ-1GN0R00C)
R247  value 0 Ω  [0201]  (hidden comment: ERJ-1GN0R00C)
R248  value 0 Ω  [0201]  (hidden comment: ERJ-1GN0R00C)
T1  BAL-0032SSG  [BAL-0032SSG]
U1  DAC39RF20ANH  [ANH0289A]  (parts A,B,C,D,E of 8)
U55  TMP451AIDQFR  [DQF0008A]

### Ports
0SRX_n (in, see 17), 0SRX_p (in, see 17), 1SRX_n (in, see 17), 1SRX_p (in, see 17), 2SRX_n (in, see 17), 2SRX_p (in, see 17), 3SRX_n (in, see 17), 3SRX_p (in, see 17), 4SRX_n (in, see 19), 4SRX_p (in, see 19), 5SRX_n (in, see 17), 5SRX_p (in, see 17), 6SRX_n (in, see 19), 6SRX_p (in, see 19), 7SRX_n (in, see 17), 7SRX_p (in, see 17), 8SRX_n (in, see 19), 8SRX_p (in, see 19), 9SRX_n (in, see 17), 9SRX_p (in, see 17), 10SRX_n (in, see 19), 10SRX_p (in, see 19), 11SRX_n (in, see 17), 11SRX_p (in, see 17), 12SRX_n (in, see 19), 12SRX_p (in, see 19), 13SRX_n (in, see 17), 13SRX_p (in, see 17), 14SRX_n (in, see 19), 14SRX_p (in, see 19), 15SRX_n (in, see 17), 15SRX_p (in, see 17), DAC_ALARM (out, see 11), DAC_SCLK (in, see 12), DAC_SDI (in, see 12), DAC_SDO (out, see 12), DAC_SYSREF_LMK_N (in, see 13), DAC_SYSREF_LMK_P (in, see 13), DAC_TXEN0 (in, see 11), DAC_TXEN1 (in, see 11), DAC_~{CS} (in, see 12), DAC_~{RESET} (in, see 11), DACOUTA_n (out, see 15), DACOUTA_p (out, see 15), DACOUTB_n (out, see 15), DACOUTB_p (out, see 15), FMC_TRIG0 (in, see 18), FMC_TRIG1 (in, see 18), FMC_TRIG2 (in, see 18), FMC_TRIG3 (in, see 18), FMC_TRIG4 (in, see 18), FMC_TRIGCLK (in, see 18), SCL_I2C (in, see 11, 17), SDA_I2C (bidir, see 11, 17), ~{SYNC}_DAC (out, see 11)

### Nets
3p3V_Utility: C217.2 R176.2 R177.2 U55.1(V+)
GND: C217.1 C219.1 J7.2 J7.3 J7.4 J8.2 J9.2 J9.3 J9.4 J10.2 J11.2 J12.2 J13.2 J13.3 J13.4 J14.2 J14.3 J14.4 R181.1 T1.4(PAD) U55.5(GND)
0SRX_DUT_n: C179.1 U1.A8(0SRX+)
0SRX_DUT_p: C178.1 U1.A7(0SRX-)
0SRX_n: C179.2 ; port 0SRX_n
0SRX_p: C178.2 ; port 0SRX_p
1SRX_DUT_n: C181.1 U1.B8(1SRX+)
1SRX_DUT_p: C180.1 U1.B7(1SRX-)
1SRX_n: C181.2 ; port 1SRX_n
1SRX_p: C180.2 ; port 1SRX_p
2SRX_DUT_n: C187.1 U1.A5(2SRX+)
2SRX_DUT_p: C185.1 U1.A4(2SRX-)
2SRX_n: C187.2 ; port 2SRX_n
2SRX_p: C185.2 ; port 2SRX_p
3SRX_DUT_n: C189.1 U1.B5(3SRX+)
3SRX_DUT_p: C188.1 U1.B4(3SRX-)
3SRX_n: C189.2 ; port 3SRX_n
3SRX_p: C188.2 ; port 3SRX_p
4SRX_DUT_n: C193.1 U1.C1(4SRX+)
4SRX_DUT_p: C191.1 U1.D1(4SRX-)
4SRX_n: C193.2 ; port 4SRX_n
4SRX_p: C191.2 ; port 4SRX_p
5SRX_DUT_n: C195.1 U1.C2(5SRX+)
5SRX_DUT_p: C194.1 U1.D2(5SRX-)
5SRX_n: C195.2 ; port 5SRX_n
5SRX_p: C194.2 ; port 5SRX_p
6SRX_DUT_n: C198.1 U1.F1(6SRX+)
6SRX_DUT_p: C196.1 U1.G1(6SRX-)
6SRX_n: C198.2 ; port 6SRX_n
6SRX_p: C196.2 ; port 6SRX_p
7SRX_DUT_n: C200.1 U1.F2(7SRX+)
7SRX_DUT_p: C199.1 U1.G2(7SRX-)
7SRX_n: C200.2 ; port 7SRX_n
7SRX_p: C199.2 ; port 7SRX_p
8SRX_DUT_n: C202.1 U1.U7(8SRX+)
8SRX_DUT_p: C201.1 U1.U8(8SRX-)
8SRX_n: C202.2 ; port 8SRX_n
8SRX_p: C201.2 ; port 8SRX_p
9SRX_DUT_n: C204.1 U1.T7(9SRX+)
9SRX_DUT_p: C203.1 U1.T8(9SRX-)
9SRX_n: C204.2 ; port 9SRX_n
9SRX_p: C203.2 ; port 9SRX_p
10SRX_DUT_n: C206.1 U1.U4(10SRX+)
10SRX_DUT_p: C205.1 U1.U5(10SRX-)
10SRX_n: C206.2 ; port 10SRX_n
10SRX_p: C205.2 ; port 10SRX_p
11SRX_DUT_n: C208.1 U1.T4(11SRX+)
11SRX_DUT_p: C207.1 U1.T5(11SRX-)
11SRX_n: C208.2 ; port 11SRX_n
11SRX_p: C207.2 ; port 11SRX_p
12SRX_DUT_n: C210.1 U1.P1(12SRX+)
12SRX_DUT_p: C209.1 U1.R1(12SRX-)
12SRX_n: C210.2 ; port 12SRX_n
12SRX_p: C209.2 ; port 12SRX_p
13SRX_DUT_n: C212.1 U1.P2(13SRX+)
13SRX_DUT_p: C211.1 U1.R2(13SRX-)
13SRX_n: C212.2 ; port 13SRX_n
13SRX_p: C211.2 ; port 13SRX_p
14SRX_DUT_n: C214.1 U1.L1(14SRX+)
14SRX_DUT_p: C213.1 U1.M1(14SRX-)
14SRX_n: C214.2 ; port 14SRX_n
14SRX_p: C213.2 ; port 14SRX_p
15SRX_DUT_n: C216.1 U1.L2(15SRX+)
15SRX_DUT_p: C215.1 U1.M2(15SRX-)
15SRX_n: C216.2 ; port 15SRX_n
15SRX_p: C215.2 ; port 15SRX_p
DAC_ALARM: PP56.1 U1.E3(ALARM) ; port DAC_ALARM
DAC_~{CS}: U1.K3(~{SCS}) ; port DAC_~{CS}
DAC_~{RESET}: PP61.1 U1.E5(~{RESET}) ; port DAC_~{RESET}
DAC_SCLK: U1.J1(SCLK) ; port DAC_SCLK
DAC_SDI: U1.J3(SDI) ; port DAC_SDI
DAC_SDO: U1.J2(SDO) ; port DAC_SDO
DAC_SYSREF_LMK_N: R173.2 ; port DAC_SYSREF_LMK_N
DAC_SYSREF_LMK_P: R171.2 ; port DAC_SYSREF_LMK_P
DAC_TXEN0: PP63.1 U1.G3(TXEN0) ; port DAC_TXEN0
DAC_TXEN1: PP64.1 U1.H3(TXEN1) ; port DAC_TXEN1
DACCLK_N: C190.1 C192.2 U1.P17(DACCLK-)
DACCLK_P: C183.2 C186.1 U1.N17(DACCLK+)
DACOUTA_n: U1.A13(DACOUTA-) ; port DACOUTA_n
DACOUTA_p: U1.A11(DACOUTA+) ; port DACOUTA_p
DACOUTB_n: U1.U13(DACOUTB-) ; port DACOUTB_n
DACOUTB_p: U1.U11(DACOUTB+) ; port DACOUTB_p
EXTR: C219.2 R179.1 U1.K17(EXTREF)
FMC_TRIG0: R244.1 ; port FMC_TRIG0
FMC_TRIG1: R245.1 ; port FMC_TRIG1
FMC_TRIG2: R246.1 ; port FMC_TRIG2
FMC_TRIG3: R247.1 ; port FMC_TRIG3
FMC_TRIG4: R248.1 ; port FMC_TRIG4
FMC_TRIGCLK: R243.1 ; port FMC_TRIGCLK
RB+: PP54.1 R175.1 U1.J17(RBIASp)
RB-: PP47.1 R175.2 U1.H17(RBIASn)
~{SYNC}_DAC: PP59.1 U1.E4(~{SYNC}) ; port ~{SYNC}_DAC
SCL_I2C: U55.8(SCL) ; port SCL_I2C
SDA_I2C: U55.7(SDA) ; port SDA_I2C
SYSREF_N: R173.1 R174.1 U1.E17(SYSREF-)
SYSREF_P: R171.1 R172.1 U1.D17(SYSREF+)
TMSTPA_N: J10.1 U1.A16(TMSTPA-)
TMSTPA_P: J8.1 U1.A15(TMSTPA+)
TMSTPB_N: J12.1 U1.U16(TMSTPB-)
TMSTPB_P: J11.1 U1.U15(TMSTPB+)
NetC182_1: C182.1 C183.1
NetC182_2: C182.2 C184.2 J7.1
NetC184_1: C184.1 T1.1(SE)
NetC186_2: C186.2 T1.2(D+)
NetC190_2: C190.2 T1.3(D-)
NetC192_1: C192.1 C197.1
NetC197_2: C197.2 J9.1
NetC218_1: C218.1 R180.2 U55.3(D-)
NetC218_2: C218.2 R178.2 U55.2(D+)
NetJ13_1: J13.1 R172.2
NetJ14_1: J14.1 R174.2
NetPP48_1: PP48.1 R243.2 U1.D4(TRIGCLK)
NetPP49_1: PP49.1 R244.2 U1.D9(TRIG0)
NetPP50_1: PP50.1 R245.2 U1.D8(TRIG1)
NetPP51_1: PP51.1 R246.2 U1.D7(TRIG2)
NetPP52_1: PP52.1 R247.2 U1.D6(TRIG3)
NetPP53_1: PP53.1 R248.2 U1.D5(TRIG4)
NetPP55_1: PP55.1 R178.1 U1.P10(TEMPDIODEp)
NetPP57_1: PP57.1 R179.2
NetPP58_1: PP58.1 U1.P9(ATEST)
NetPP60_1: PP60.1 R180.1 U1.R10(TEMPDIODEn)
NetPP62_1: PP62.1 R181.2 U1.F3(SCANEN)
NetR176_1: R176.1 U55.6(~{ALERT}_~{THERM2})
NetR177_1: R177.1 U55.4(~{THERM})

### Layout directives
differential pair: 0SRX_DUT_n, 0SRX_DUT_p, 1SRX_DUT_n, 1SRX_DUT_p, 2SRX_DUT_n, 2SRX_DUT_p, 3SRX_DUT_n, 3SRX_DUT_p, 4SRX_DUT_n, 4SRX_DUT_p, 5SRX_DUT_n, 5SRX_DUT_p, 6SRX_DUT_n, 6SRX_DUT_p, 7SRX_DUT_n, 7SRX_DUT_p, 8SRX_DUT_n, 8SRX_DUT_p, 9SRX_DUT_n, 9SRX_DUT_p, 10SRX_DUT_n, 10SRX_DUT_p, 11SRX_DUT_n, 11SRX_DUT_p, 12SRX_DUT_n, 12SRX_DUT_p, 13SRX_DUT_n, 13SRX_DUT_p, 14SRX_DUT_n, 14SRX_DUT_p, 15SRX_DUT_n, 15SRX_DUT_p, TMSTPA_N, TMSTPA_P, TMSTPB_N, TMSTPB_P
net class SERDES: 0SRX_DUT_n, 0SRX_DUT_p, 1SRX_DUT_n, 1SRX_DUT_p, 2SRX_DUT_n, 2SRX_DUT_p, 3SRX_DUT_n, 3SRX_DUT_p, 4SRX_DUT_n, 4SRX_DUT_p, 5SRX_DUT_n, 5SRX_DUT_p, 6SRX_DUT_n, 6SRX_DUT_p, 7SRX_DUT_n, 7SRX_DUT_p, 8SRX_DUT_n, 8SRX_DUT_p, 9SRX_DUT_n, 9SRX_DUT_p, 10SRX_DUT_n, 10SRX_DUT_p, 11SRX_DUT_n, 11SRX_DUT_p, 12SRX_DUT_n, 12SRX_DUT_p, 13SRX_DUT_n, 13SRX_DUT_p, 14SRX_DUT_n, 14SRX_DUT_p, 15SRX_DUT_n, 15SRX_DUT_p
net class Clocks&SYSREF: NetC182_2, NetC197_2, NetJ13_1, NetJ14_1

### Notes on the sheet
- SYSREF from LMK is AC Coupled on LMK page
- (near U55) Addr : 0x4C

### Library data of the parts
?#1-?#3 = Swizzle: Schematic notation to show that the pads of two components should be overlapped
C178-C181 C185 C187-C189 C191 C193-C196 C198-C216 = 0201RFCaps0693: Broadband Capacitors; Manufacturer: Passive Plus; Alt PartNumber: GRM033C71C104ME14D; Alt Manufacturer: Murata Electronics; SizeZ_mm: 0.33; SizeX_mm: 0.58; SizeY_mm: 0.3; CompType: Capactior RF; Tolerance: ±10%; Temperature Coefficient: C0G, NP0
C182-C184 C186 C190 C192 C197 = 0201RFCaps0693: Broadband Capacitors; Manufacturer: Passive Plus; Alt PartNumber: GRM033C71C104ME14D; Alt Manufacturer: Murata Electronics; CompType: Capactior RF; Tolerance: ±10%; Temperature Coefficient: C0G, NP0; SizeX_mm: 0.58; SizeY_mm: 0.3; SizeZ_mm: 0.33
C217 = capcc09263: as C160 on sheet Clocking LMK04828
C218 = capcc08503: CAP CER MLCC; Manufacturer: Murata Electronics; CompType: Capacitor Ceramic; Tolerance: ±5%; Temperature Coefficient: X7R; SizeX_mm: 0.6; SizeY_mm: 0.3; SizeZ_mm: 0.33
C219 = CMP-0064970-1: CAP, CERM, 0.1 uF, 16 V,+/- 10%, X7R, 0201; Manufacturer: MuRata; TaMin_C: -55°C; Polarized: N; SizeAreaWB_mm2: 2.08; Value1: Unknown; U/M: EA; Value: 0.1uF; TaMax_C: 125°C; SizeZ_mm: 0.26; SizeX_mm: 0.6; SizeY_mm: 0.3; Cap_Case: 0201; Value2: 16V; SizeArea_mm2: 0.18; Cap_F: 100nF; AEC Category: Q200
J7 J9 J13 J14 = cmp00522: 2.92mm Connector Receptacle, Female Socket 50 Ohms Board Edge, End Launch Compression; PartNumber: KCC198709; Manufacturer: KonnectRF; Alt Manufacturer: HiRose; CompType: RF Connector; Notes: TI Supplied
J8 J10-J12 = cmp00032: SMP Connector Plug, Male Pin 50Ohm Surface Mount Solder; Manufacturer: Molex; SymbolCreator: a0799628; Cert_UL: Y; ContactFinish: Gold; CompType: RF Connector; CT: False; Voltage_V: 335V
PP47-PP64 = Probe Point: as PP32-PP39 on sheet LMK LVL Shift and Mux
R171-R174 R181 R243-R248 = RSMD020101699: RES SMD 0 OHM JUMPER 1/20W 0201; Manufacturer: Panasonic Electronic Components; CompType: Resistor SMD; Power (Watts): 0.05W, 1/20W
R175 = RSMD020100620: RES SMD 3.6K OHM 1% 1/20W 0201; Manufacturer: Panasonic Electronic Components; CompType: Resistor SMD; Power (Watts): 0.05W, 1/20W; Temperature Coefficient: ±200ppm/°C
R176 R177 = RSMD020100735: RES 10K OHM 1% 1/20W 0201 SMD; Manufacturer: Panasonic Electronic Components; CompType: Resistor SMD; Power (Watts): 0.05W, 1/20W; Temperature Coefficient: ±200ppm/°C
R178 R180 = RSMD020100289: RES SMD 100 OHM 1% 1/20W 0201; Manufacturer: Panasonic Electronic Components; CompType: Resistor SMD; Power (Watts): 0.05W, 1/20W; Temperature Coefficient: ±200ppm/°C
R179 = RSMD020100143: RES SMD 1K OHM 1% 1/20W 0201; Manufacturer: Panasonic Electronic Components; CompType: Resistor SMD; Power (Watts): 0.05W, 1/20W; Temperature Coefficient: ±200ppm/°C
T1 = cmp00464: Balun, 10 to 32000 MHz, 1 W Pwr Handling, 8 dB IL, +/- 0.5 dB Amp. Var,; Manufacturer: Marki Microwave
U1 = cmp00515: Manufacturer: Texas Instruments; CompType: DAC
U55 = TMP451AIDQF: 1.7V-Capable Remote and Local Temp Sensor with Auto Beta, N-Factor, Filter, and Series-R Correction, DQF0008A (WSON-8); Alternate PartNumber: TMP451AIDQFT; Alternate Manufacturer: Texas Instruments; Green_Lifecycle: Active; SizeAreaWB_mm2: 9.0; Green_REACh: Passed; U/M: EA; SizeZ_mm: 0.8; SizeX_mm: 2.0; SizeArea_mm2: 4.0; CompType: IC; SymbolCreator: a0411947

## Sheet DUT Outputs.SchDoc: DAC Outputs
size 431 x 279 mm; Date: Not shown in title block; ApprovedBy: Not shown in title block; CheckedBy: Not shown in title block; Author: Not shown in title block; CompanyName: Not shown in title block; Engineer: Not shown in title block; Organization: Not shown in title block; Address1: Not shown in title block; Address2: Not shown in title block; Address3: Not shown in title block; Address4: Not shown in title block; DocumentNumber: 1; Revision: Use project parameter SCH_Rev; SheetNumber: 15; SheetTotal: 21; PageSetup: Record=PageOptions¦CenterHorizontal=True¦CenterVertical=True¦PrintScale=1.00¦XCorrection=1.00¦YCorrection=1.00¦PrintKind=0¦BorderSize=5000000¦LeftOffset=0¦BottomOffset=0¦Orientation=2¦PaperLength=1000¦PaperWidth=1000¦Scale=100¦PaperSource=15¦PrintQuality=600¦MediaType=1¦DitherType=10¦PaperKind=Letter¦PrintScaleMode=1
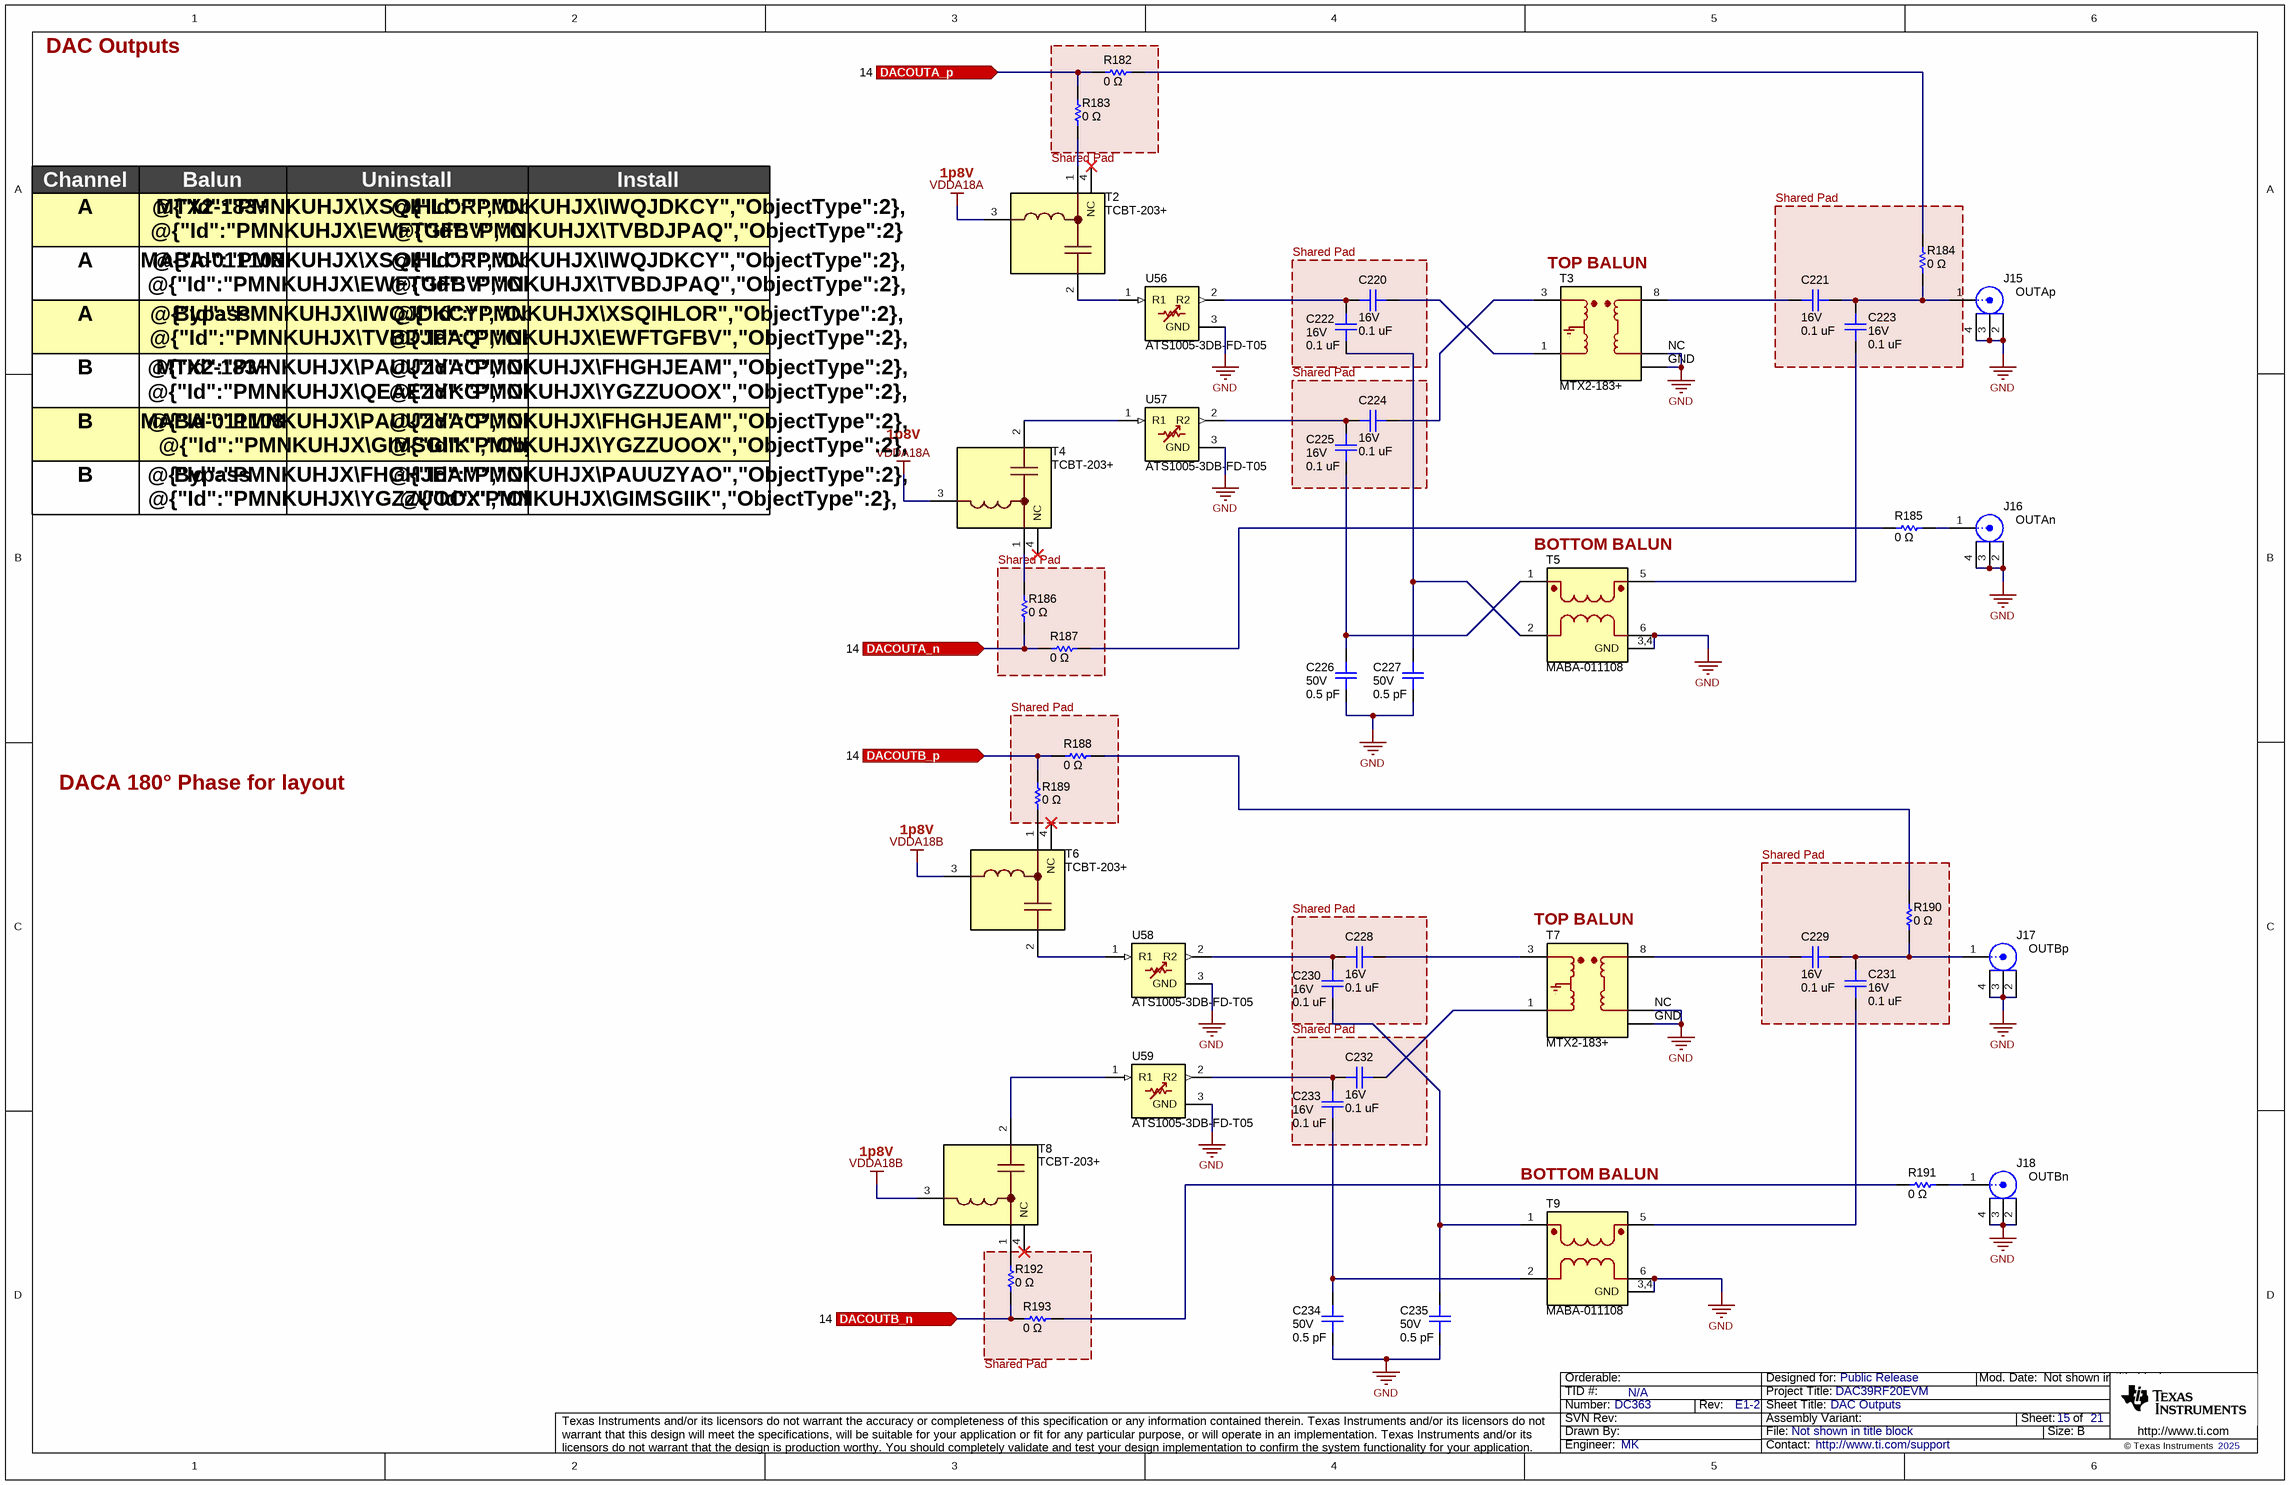
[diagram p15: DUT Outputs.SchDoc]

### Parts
(Parts that share a designator on the sheet are numbered #1, #2 ... from top to bottom, then left to right.)
?#4  Shared Pad  (graphical)
?#5  Shared Pad  (graphical)
?#6  Shared Pad  (graphical)
?#7  Shared Pad  (graphical)
?#8  Shared Pad  (graphical)
?#9  Shared Pad  (graphical)
?#10  Shared Pad  (graphical)
?#11  Shared Pad  (graphical)
?#12  Shared Pad  (graphical)
?#13  Shared Pad  (graphical)
C220  value 0.1 uF  Voltage - Rated: 16V  [0201_cap]  (hidden comment: 0201BB104KW160)
C221  value 0.1 uF  Voltage - Rated: 16V  [0201_cap]  (hidden comment: 0201BB104KW160)
C222  value 0.1 uF  Voltage - Rated: 16V  [0201_cap]  (hidden comment: 0201BB104KW160)
C223  value 0.1 uF  Voltage - Rated: 16V  [0201_cap]  (hidden comment: 0201BB104KW160)
C224  value 0.1 uF  Voltage - Rated: 16V  [0201_cap]  (hidden comment: 0201BB104KW160)
C225  value 0.1 uF  Voltage - Rated: 16V  [0201_cap]  (hidden comment: 0201BB104KW160)
C226  value 0.5 pF  Voltage - Rated: 50V  [0201_cap]  (hidden comment: GJM0335C1HR50WB01D)
C227  value 0.5 pF  Voltage - Rated: 50V  [0201_cap]  (hidden comment: GJM0335C1HR50WB01D)
C228  value 0.1 uF  Voltage - Rated: 16V  [0201_cap]  (hidden comment: 0201BB104KW160)
C229  value 0.1 uF  Voltage - Rated: 16V  [0201_cap]  (hidden comment: 0201BB104KW160)
C230  value 0.1 uF  Voltage - Rated: 16V  [0201_cap]  (hidden comment: 0201BB104KW160)
C231  value 0.1 uF  Voltage - Rated: 16V  [0201_cap]  (hidden comment: 0201BB104KW160)
C232  value 0.1 uF  Voltage - Rated: 16V  [0201_cap]  (hidden comment: 0201BB104KW160)
C233  value 0.1 uF  Voltage - Rated: 16V  [0201_cap]  (hidden comment: 0201BB104KW160)
C234  value 0.5 pF  Voltage - Rated: 50V  [0201_cap]  (hidden comment: GJM0335C1HR50WB01D)
C235  value 0.5 pF  Voltage - Rated: 50V  [0201_cap]  (hidden comment: GJM0335C1HR50WB01D)
J15  Text1: OUTAp  [HiRose-HK-LR-SR2-SWM1092-04A-MicroStirp-6mil-Female-Backdrill]  (hidden comment: HK-LR-SR2(11))
J16  Text1: OUTAn  [HiRose-HK-LR-SR2-SWM1092-04A-MicroStirp-6mil-Female-Backdrill]  (hidden comment: HK-LR-SR2(11))
J17  Text1: OUTBp  [HiRose-HK-LR-SR2-SWM1092-04A-MicroStirp-6mil-Female-Backdrill]  (hidden comment: HK-LR-SR2(11))
J18  Text1: OUTBn  [HiRose-HK-LR-SR2-SWM1092-04A-MicroStirp-6mil-Female-Backdrill]  (hidden comment: HK-LR-SR2(11))
R182  value 0 Ω  [0201]  (hidden comment: ERJ-1GN0R00C)
R183  value 0 Ω  [0201]  (hidden comment: ERJ-1GN0R00C)
R184  value 0 Ω  [0201]  (hidden comment: ERJ-1GN0R00C)
R185  value 0 Ω  [0201]  (hidden comment: ERJ-1GN0R00C)
R186  value 0 Ω  [0201]  (hidden comment: ERJ-1GN0R00C)
R187  value 0 Ω  [0201]  (hidden comment: ERJ-1GN0R00C)
R188  value 0 Ω  [0201]  (hidden comment: ERJ-1GN0R00C)
R189  value 0 Ω  [0201]  (hidden comment: ERJ-1GN0R00C)
R190  value 0 Ω  [0201]  (hidden comment: ERJ-1GN0R00C)
R191  value 0 Ω  [0201]  (hidden comment: ERJ-1GN0R00C)
R192  value 0 Ω  [0201]  (hidden comment: ERJ-1GN0R00C)
R193  value 0 Ω  [0201]  (hidden comment: ERJ-1GN0R00C)
T2  TCBT-203+  [GU1414-4]
T3  MTX2-183+  [DG3006]
T4  TCBT-203+  [GU1414-4]
T5  MABA-011108  [MABA-011108]
T6  TCBT-203+  [GU1414-4]
T7  MTX2-183+  [DG3006]
T8  TCBT-203+  [GU1414-4]
T9  MABA-011108  [MABA-011108]
U56  ATS1005-3DB-FD-T05  [SUSUMU_ATS1005]
U57  ATS1005-3DB-FD-T05  [SUSUMU_ATS1005]
U58  ATS1005-3DB-FD-T05  [SUSUMU_ATS1005]
U59  ATS1005-3DB-FD-T05  [SUSUMU_ATS1005]

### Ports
DACOUTA_n (in, see 14), DACOUTA_p (in, see 14), DACOUTB_n (in, see 14), DACOUTB_p (in, see 14)

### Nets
GND: C226.2 C227.2 C234.2 C235.2 J15.2 J15.3 J15.4 J16.2 J16.3 J16.4 J17.2 J17.3 J17.4 J18.2 J18.3 J18.4 T3.2,13(GND) T3.4,5,6,7,9,10,11,12(NC) T5.3,4(GND) T5.6 T7.2,13(GND) T7.4,5,6,7,9,10,11,12(NC) T9.3,4(GND) T9.6 U56.3(GND) U57.3(GND) U58.3(GND) U59.3(GND)
VDDA18A: T2.3(DC) T4.3(DC)
VDDA18B: T6.3(DC) T8.3(DC)
DACOUTA_n: R186.1 R187.1 ; port DACOUTA_n
DACOUTA_p: R182.1 R183.1 ; port DACOUTA_p
DACOUTB_n: R192.1 R193.1 ; port DACOUTB_n
DACOUTB_p: R188.1 R189.1 ; port DACOUTB_p
NetC220_1: C220.1 T3.1(Secondary)
NetC220_2: C220.2 C222.2 U56.2(R2)
NetC221_1: C221.1 C223.1 J15.1 R184.1
NetC221_2: C221.2 T3.8(Primary_Dot)
NetC222_1: C222.1 C227.1 T5.2
NetC223_2: C223.2 T5.5(secondary_dot)
NetC224_1: C224.1 T3.3(Secondary_Dot)
NetC224_2: C224.2 C225.2 U57.2(R2)
NetC225_1: C225.1 C226.1 T5.1(primary_dot)
NetC228_1: C228.1 T7.3(Secondary_Dot)
NetC228_2: C228.2 C230.2 U58.2(R2)
NetC229_1: C229.1 C231.1 J17.1 R190.1
NetC229_2: C229.2 T7.8(Primary_Dot)
NetC230_1: C230.1 C235.1 T9.1(primary_dot)
NetC231_2: C231.2 T9.5(secondary_dot)
NetC232_1: C232.1 T7.1(Secondary)
NetC232_2: C232.2 C233.2 U59.2(R2)
NetC233_1: C233.1 C234.1 T9.2
NetJ16_1: J16.1 R185.2
NetJ18_1: J18.1 R191.2
NetR182_2: R182.2 R184.2
NetR183_2: R183.2 T2.1(RF&DC)
NetR185_1: R185.1 R187.2
NetR186_2: R186.2 T4.1(RF&DC)
NetR188_2: R188.2 R190.2
NetR189_2: R189.2 T6.1(RF&DC)
NetR191_1: R191.1 R193.2
NetR192_2: R192.2 T8.1(RF&DC)
NetT2_2: T2.2(RF) U56.1(R1)
NetT4_2: T4.2(RF) U57.1(R1)
NetT6_2: T6.2(RF) U58.1(R1)
NetT8_2: T8.2(RF) U59.1(R1)

Not connected (* = marked no-connect by the designer): T2 4(NC)*; T4 4(NC)*; T6 4(NC)*; T8 4(NC)*

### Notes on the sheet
- (near T2) 1p8V
- Channel
- Balun
- Uninstall
- Install
- A
- MTX2-183+
- MABA-011108
- @{"Id":"PMNKUHJX\XSQIHLOR","ObjectType":2}, @{"Id":"PMNKUHJX\EWFTGFBV","ObjectType":2} @{"Id":"PMNKUHJX\RXUHYFPU","ObjectType":2}, @{"Id":"PMNKUHJX\CGLITYJZ","ObjectType":2}, @{"Id":"PMNKUHJX\TWZQSFXP","ObjectType":2}, @{"Id":"PMNKUHJX\IDTTNGGC","ObjectType":2}
- @{"Id":"PMNKUHJX\XSQIHLOR","ObjectType":2}, @{"Id":"PMNKUHJX\EWFTGFBV","ObjectType":2}, @{"Id":"PMNKUHJX\RXUHYFPU","ObjectType":2}, @{"Id":"PMNKUHJX\SNVYMXMR","ObjectType":2}, @{"Id":"PMNKUHJX\WCVONZVF","ObjectType":2}, @{"Id":"PMNKUHJX\YWTJTLVR","ObjectType":2}
- @{"Id":"PMNKUHJX\IWQJDKCY","ObjectType":2}, @{"Id":"PMNKUHJX\TVBDJPAQ","ObjectType":2} @{"Id":"PMNKUHJX\SNVYMXMR","ObjectType":2}, @{"Id":"PMNKUHJX\WCVONZVF","ObjectType":2} @{"Id":"PMNKUHJX\YWTJTLVR","ObjectType":2}
- @{"Id":"PMNKUHJX\IWQJDKCY","ObjectType":2}, @{"Id":"PMNKUHJX\TVBDJPAQ","ObjectType":2}, @{"Id":"PMNKUHJX\CGLITYJZ","ObjectType":2}, @{"Id":"PMNKUHJX\IDTTNGGC","ObjectType":2}, @{"Id":"PMNKUHJX\TWZQSFXP","ObjectType":2}
- (near T3) TOP BALUN
- Bypass
- @{"Id":"PMNKUHJX\IWQJDKCY","ObjectType":2}, @{"Id":"PMNKUHJX\TVBDJPAQ","ObjectType":2}, @{"Id":"PMNKUHJX\WCVONZVF","ObjectType":2}, @{"Id":"PMNKUHJX\TWZQSFXP","ObjectType":2}
- @{"Id":"PMNKUHJX\XSQIHLOR","ObjectType":2}, @{"Id":"PMNKUHJX\EWFTGFBV","ObjectType":2}, @{"Id":"PMNKUHJX\COEVFEIQ","ObjectType":2}
- B
- @{"Id":"PMNKUHJX\PAUUZYAO","ObjectType":2}, @{"Id":"PMNKUHJX\QEAEZYKG","ObjectType":2}, @{"Id":"PMNKUHJX\GIMSGIIK","ObjectType":2}, @{"Id":"PMNKUHJX\RCIVOTGF","ObjectType":2}, @{"Id":"PMNKUHJX\IBBDVJBY","ObjectType":2}, @{"Id":"PMNKUHJX\DHTOUIXW","ObjectType":2}
- @{"Id":"PMNKUHJX\FHGHJEAM","ObjectType":2}, @{"Id":"PMNKUHJX\YGZZUOOX","ObjectType":2}, @{"Id":"PMNKUHJX\FPIPBJKW","ObjectType":2}, @{"Id":"PMNKUHJX\NGWYQXKK","ObjectType":2}, @{"Id":"PMNKUHJX\XIHMHENB","ObjectType":2}
- (near T4) 1p8V
- @{"Id":"PMNKUHJX\PAUUZYAO","ObjectType":2}, @{"Id":"PMNKUHJX\GIMSGIIK","ObjectType":2}, @{"Id":"PMNKUHJX\QEAEZYKG","ObjectType":2}, @{"Id":"PMNKUHJX\FPIPBJKW","ObjectType":2}, @{"Id":"PMNKUHJX\XIHMHENB","ObjectType":2}, @{"Id":"PMNKUHJX\NGWYQXKK","ObjectType":2}
- @{"Id":"PMNKUHJX\FHGHJEAM","ObjectType":2}, @{"Id":"PMNKUHJX\YGZZUOOX","ObjectType":2}, @{"Id":"PMNKUHJX\RCIVOTGF","ObjectType":2}, @{"Id":"PMNKUHJX\DHTOUIXW","ObjectType":2}, @{"Id":"PMNKUHJX\IBBDVJBY","ObjectType":2}
- @{"Id":"PMNKUHJX\FHGHJEAM","ObjectType":2}, @{"Id":"PMNKUHJX\YGZZUOOX","ObjectType":2}, @{"Id":"PMNKUHJX\XIHMHENB","ObjectType":2}, @{"Id":"PMNKUHJX\IBBDVJBY","ObjectType":2}
- @{"Id":"PMNKUHJX\PAUUZYAO","ObjectType":2}, @{"Id":"PMNKUHJX\GIMSGIIK","ObjectType":2}, @{"Id":"PMNKUHJX\QEAEZYKG","ObjectType":2}
- (near T5) BOTTOM BALUN
- DACA 180° Phase for layout
- (near T6) 1p8V
- (near T7) TOP BALUN
- (near T8) 1p8V
- (near T9) BOTTOM BALUN

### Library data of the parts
?#4-?#13 = Swizzle: as ?#1 on sheet DUT IO
C220-C225 C228-C233 = 0201RFCaps0693: as C182 on sheet DUT IO
C226 C227 C234 C235 = 0201RFCaps0050: CAP CER 0.5PF 50V C0G/NP0 0201; Manufacturer: Murata Electronics; CompType: Capactior RF; Tolerance: ±0.05pF; Temperature Coefficient: C0G, NP0; SizeX_mm: 0.6; SizeY_mm: 0.3; SizeZ_mm: 0.33
J15-J18 = cmp00522: as J7 on sheet DUT IO
R182-R193 = RSMD020101699: as R171-R174 on sheet DUT IO
T2 T4 T6 T8 = TCBT-203+: MINIATURE SURFACE-MOUNT BIAS-TEE; Manufacturer: MiniCircuits; CompType: Bias Tee
T3 T7 = cmp00461: 1:2 MMIC Transformer, 2 - 18 GHz, 50Ω; Manufacturer: Mini-Circuits; CompType: Balun
T5 T9 = MABA-011108: 1:1 Transmission Line Balun / 5 MHz - 10GHz; Manufacturer: MACOM
U56-U59 = ATS1005-3DB-FD-T05: RF Attenuators 3dB 0 Hz ~ 50 GHz 50 Ohms 32mW 0402 (1005 Metric); Manufacturer: Susumu; Parameter 1: Mouser; Parameter 2: 754-ATS1005-3DBFDT05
